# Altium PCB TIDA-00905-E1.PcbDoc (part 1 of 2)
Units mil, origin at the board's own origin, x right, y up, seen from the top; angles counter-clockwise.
Board outline 3740.15 x 5314.95 mil, 4 copper layers (Top Layer, GND, PWR, Bottom Layer), stack 79.834 mil thick; 196 components, 87 nets, 593 pads, 163 vias.
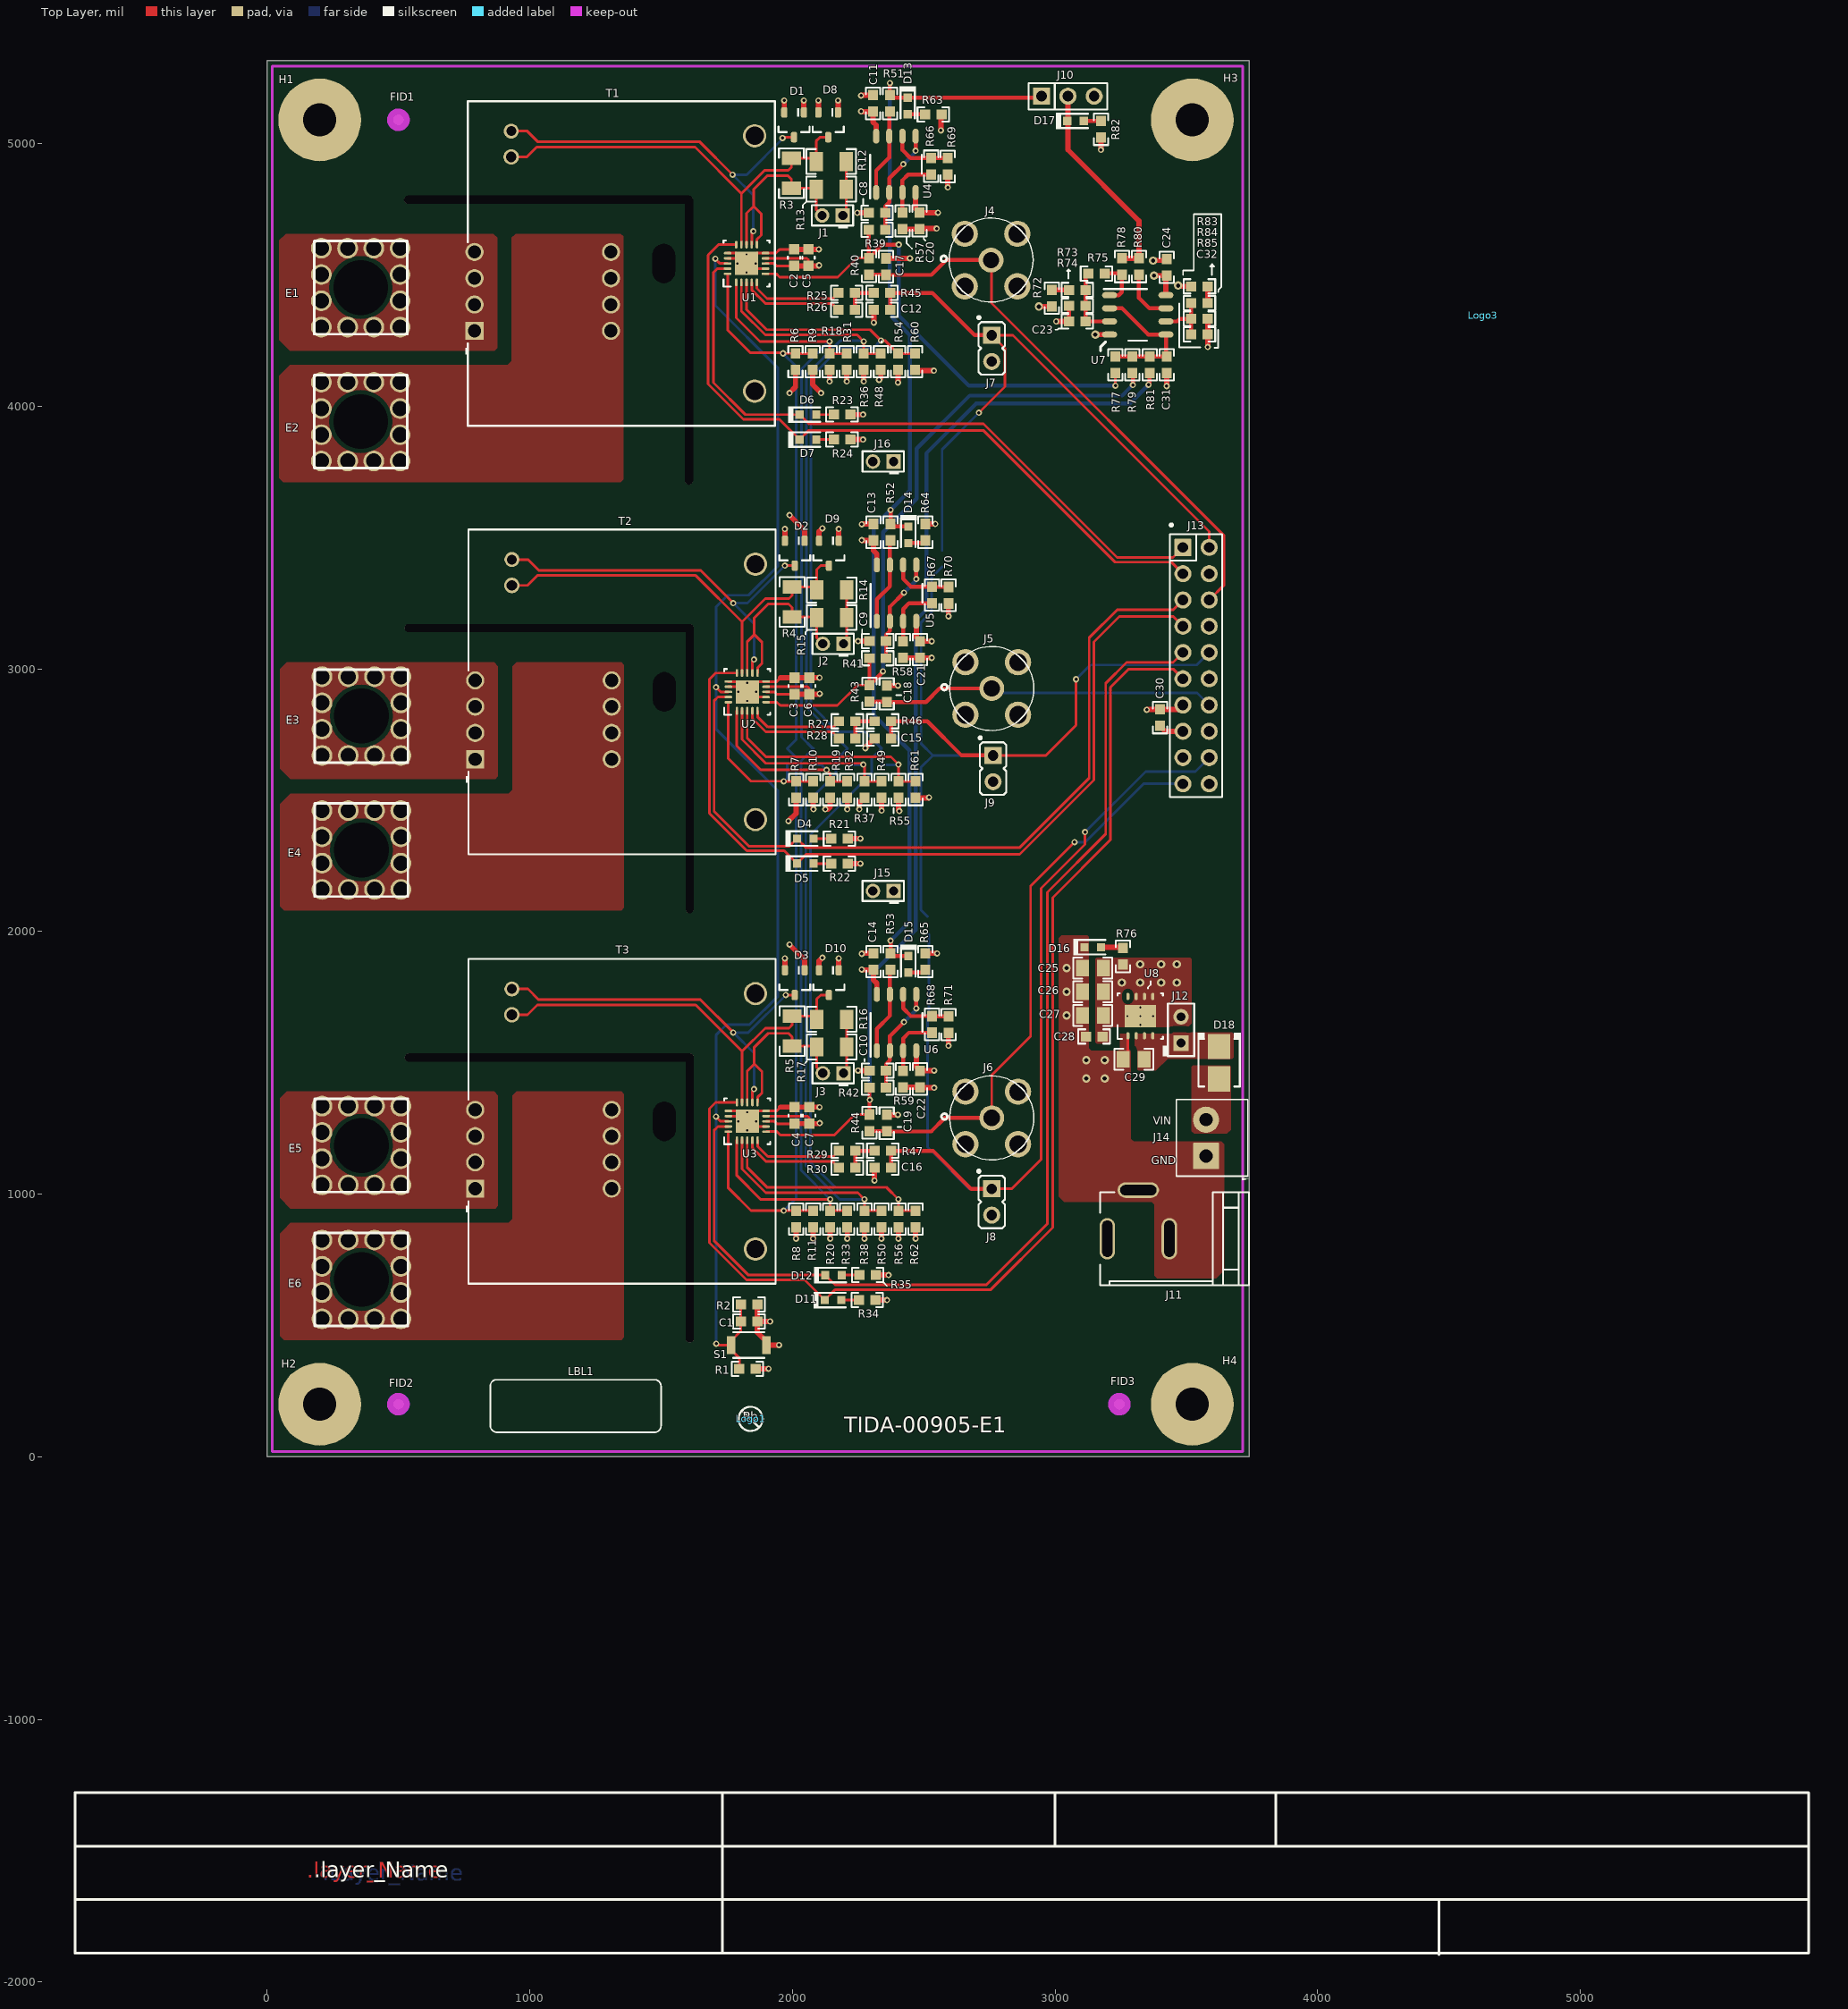
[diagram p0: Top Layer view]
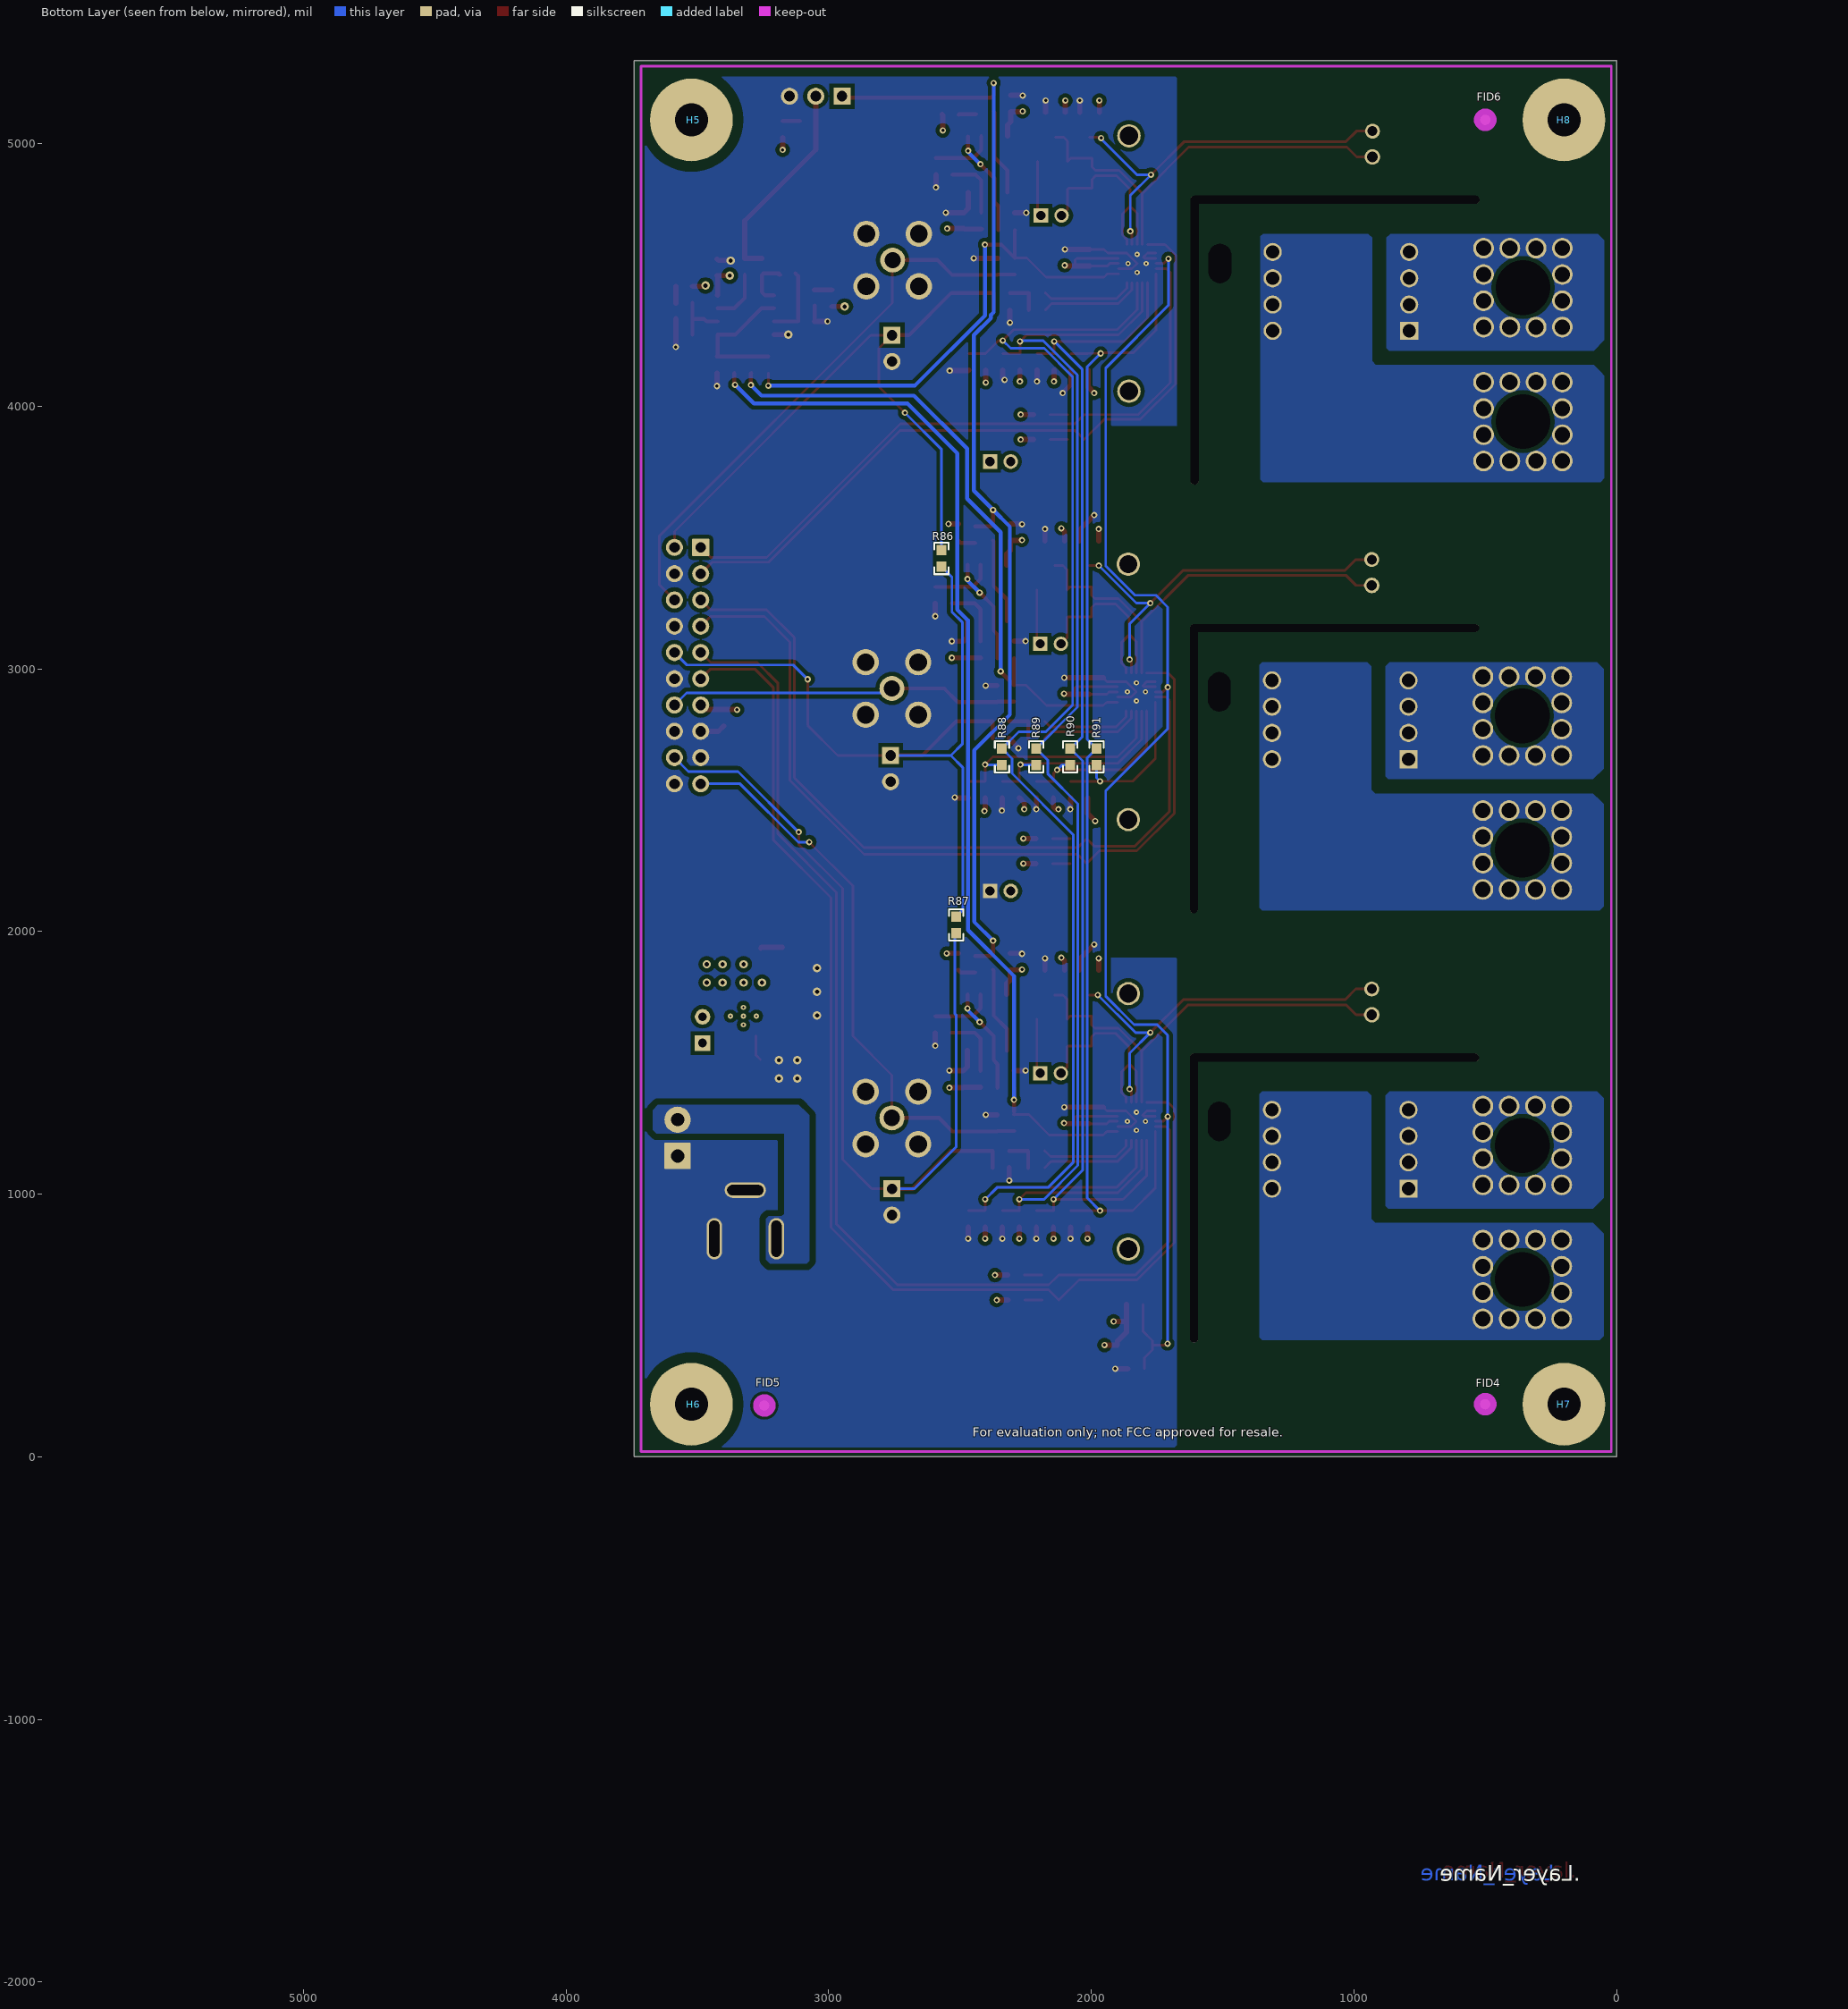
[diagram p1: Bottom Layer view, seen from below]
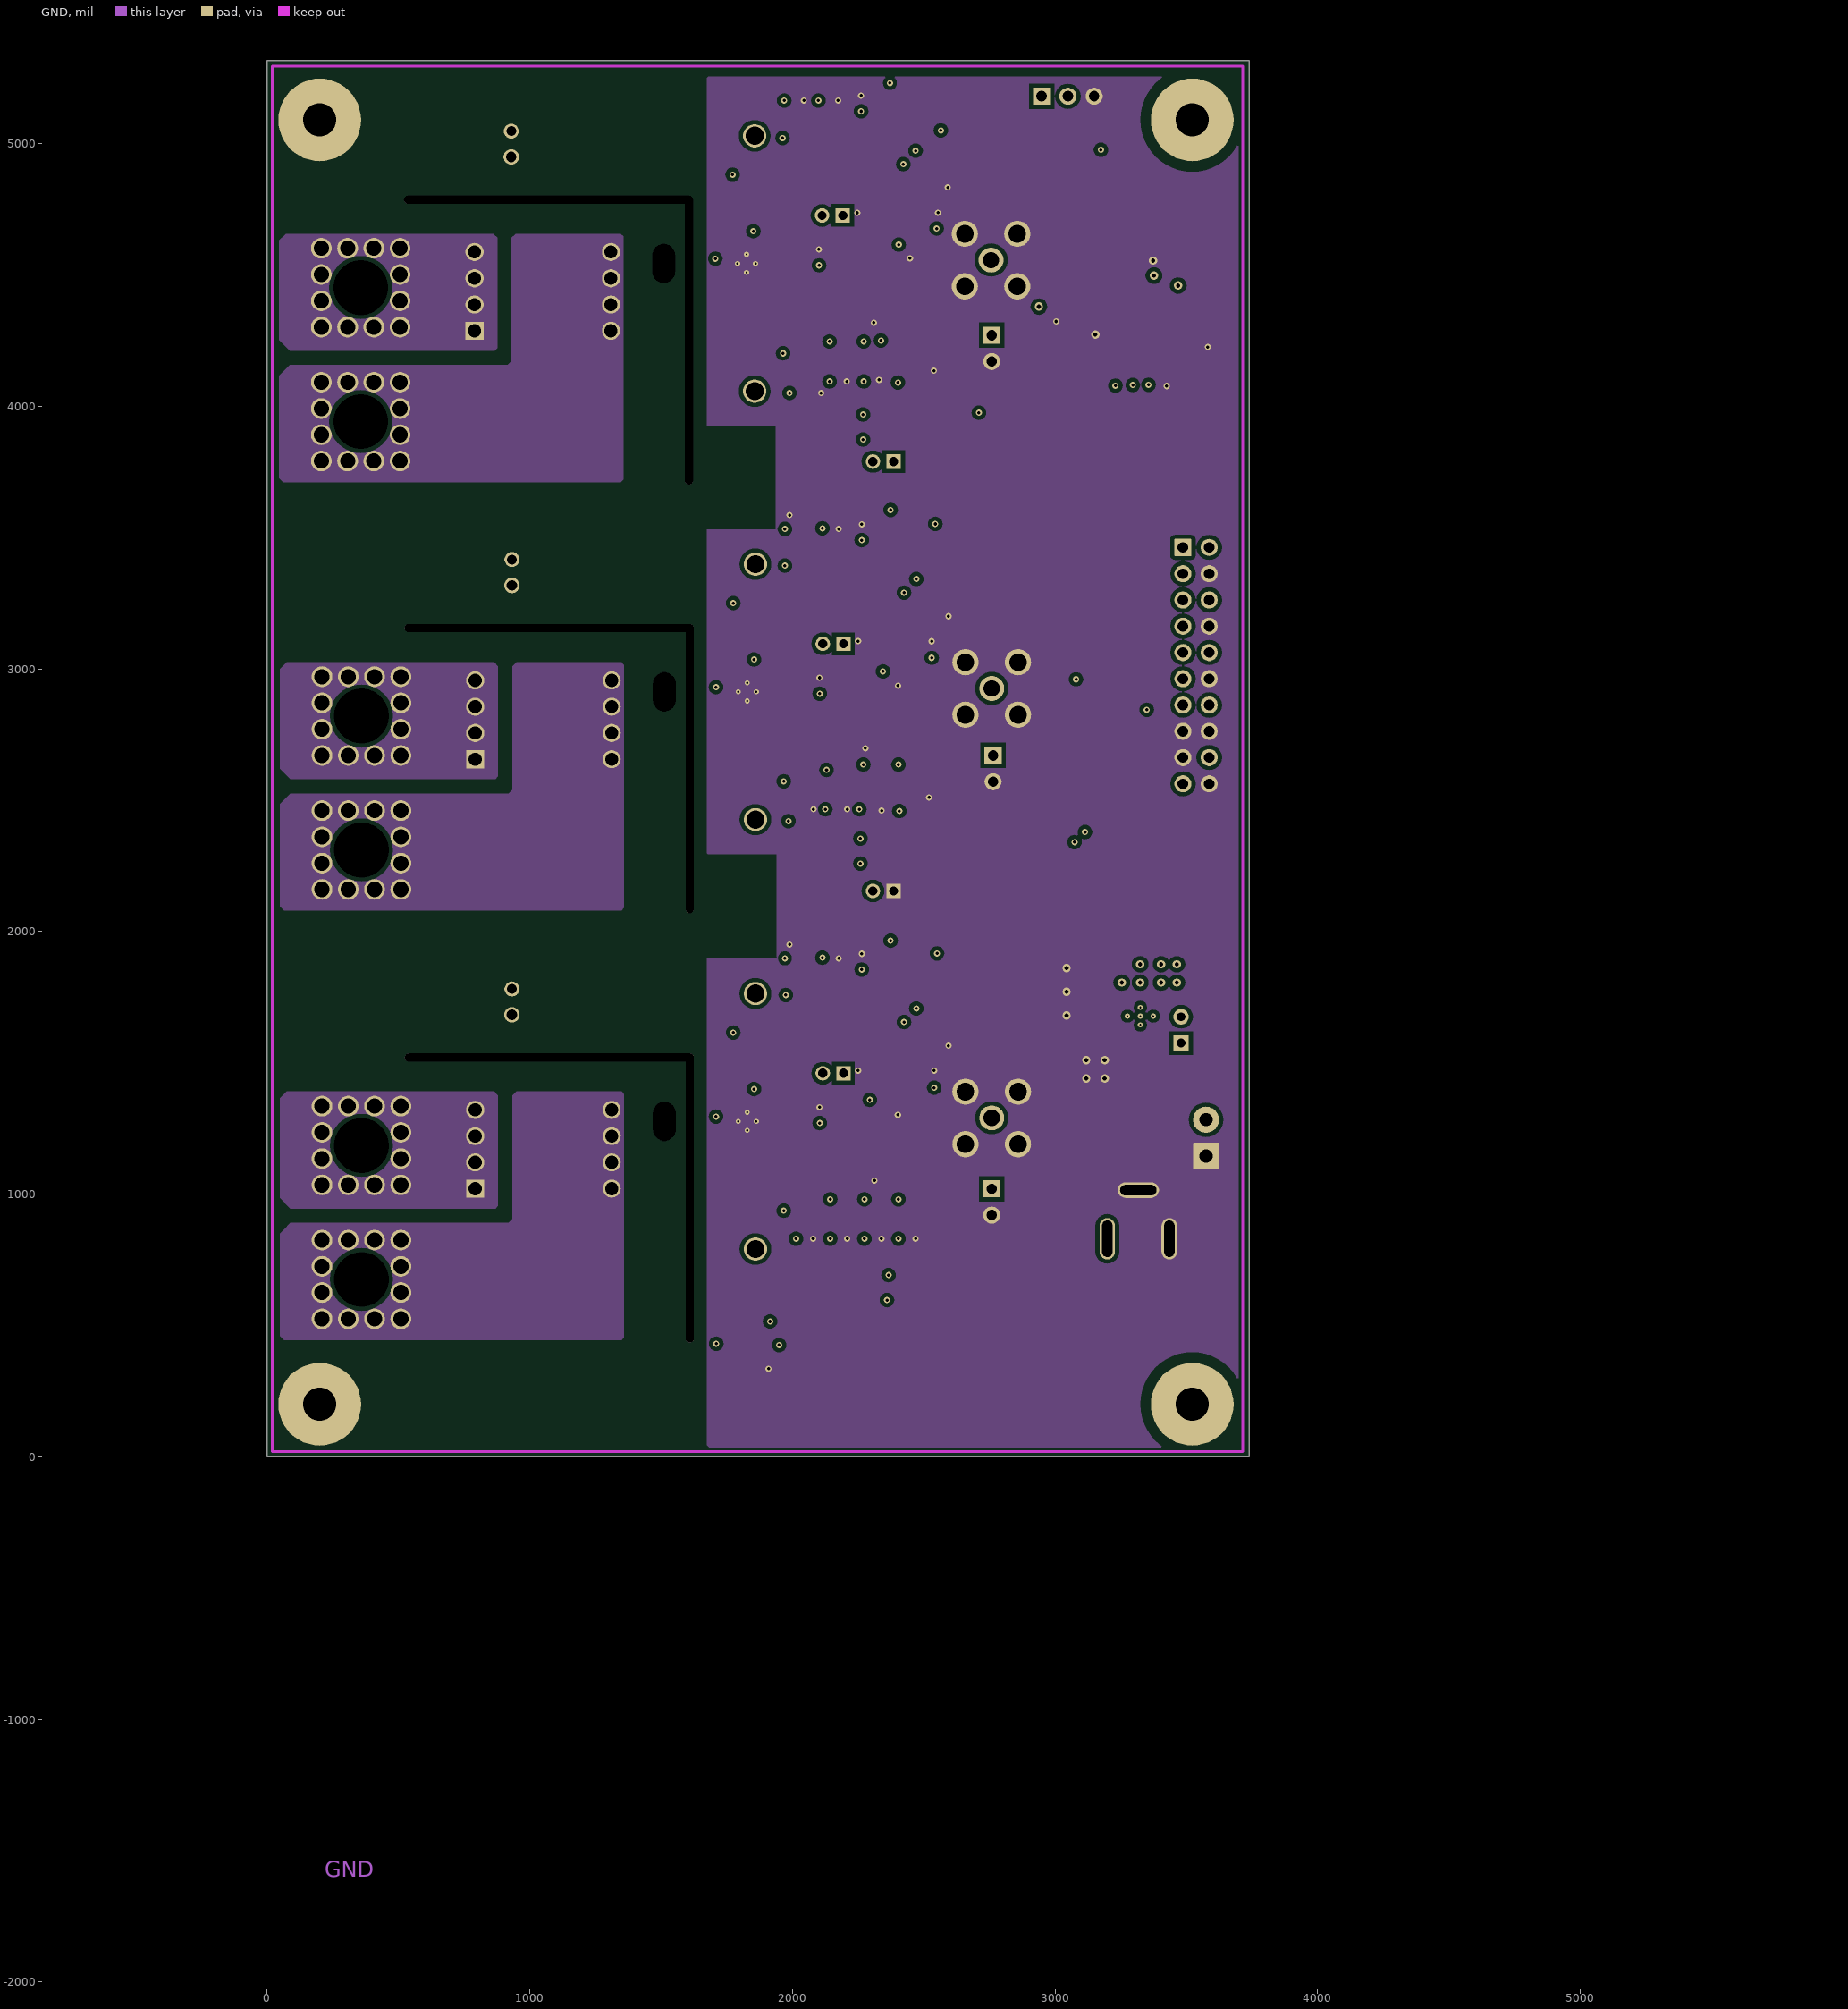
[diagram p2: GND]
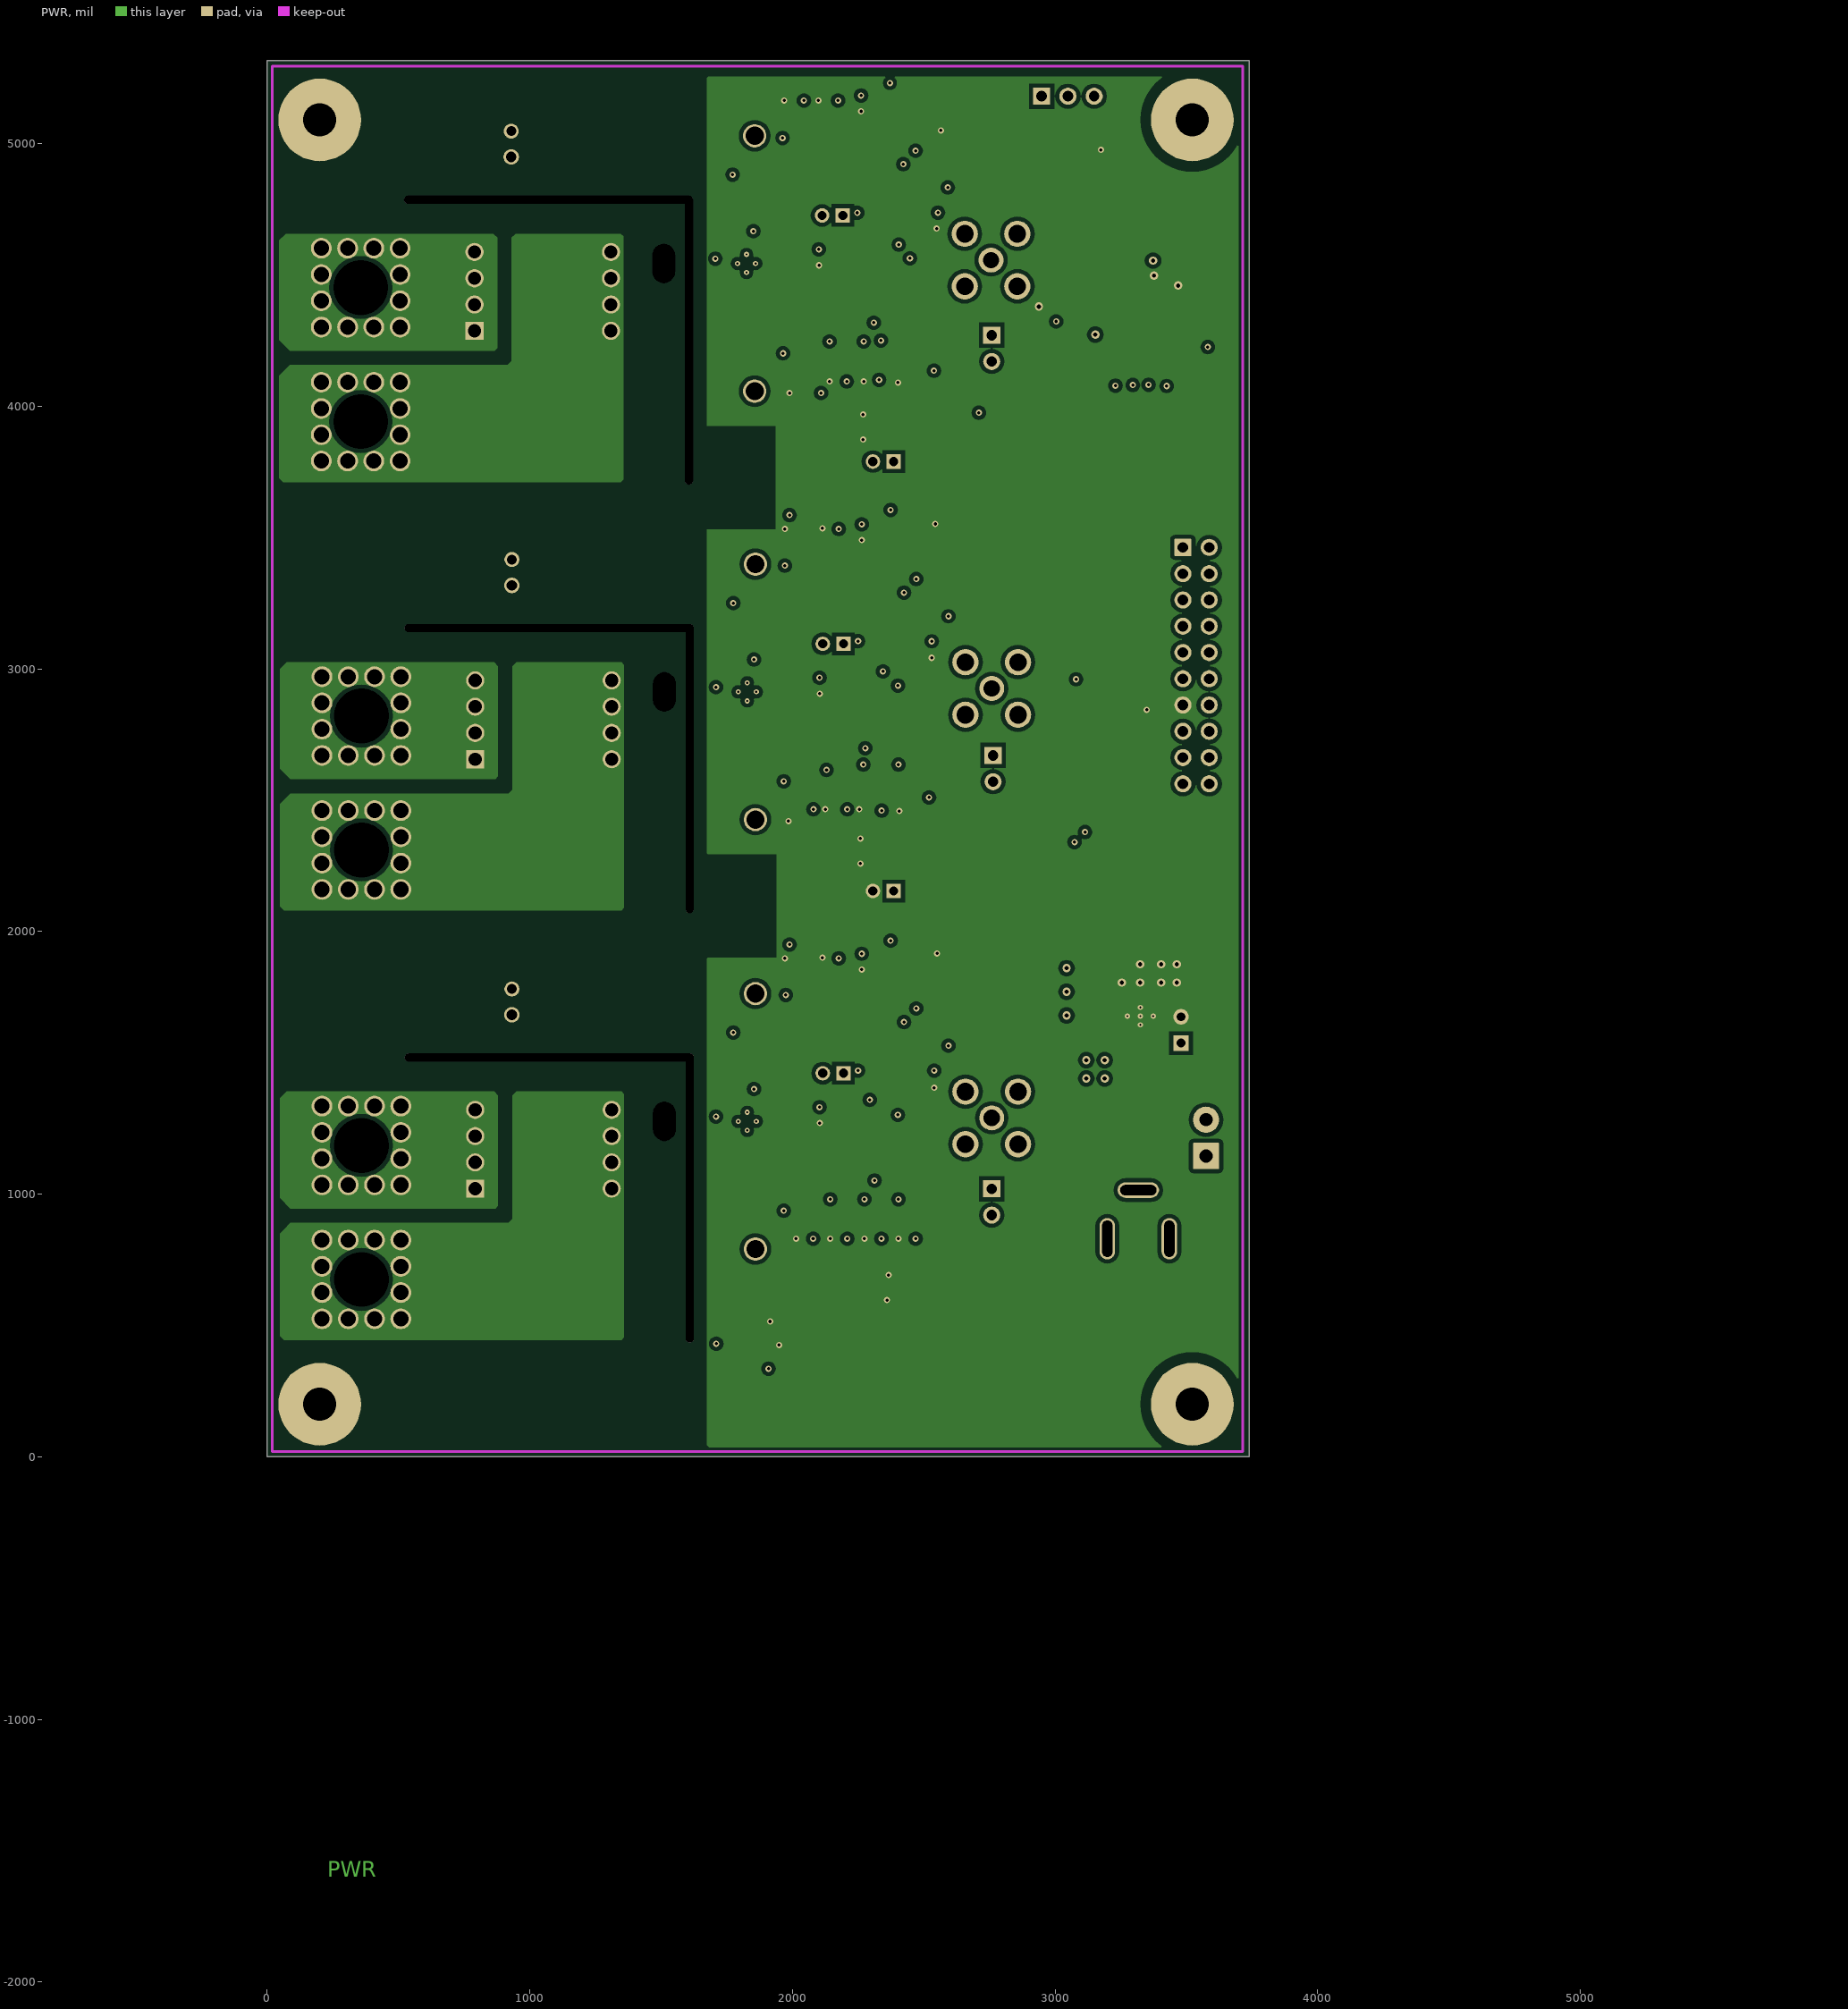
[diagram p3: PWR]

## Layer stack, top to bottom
Top Solder: solder mask 0.4, Solder Resist, Dk 3.5
Top Layer: signal copper 1.4
Dielectric1: core 59.2, FR-4, Dk 4.8
GND: signal copper 1.417
Dielectric 2: prepreg 5, Dk 4.2
PWR: signal copper 1.417
Dielectric 3: core 10, Dk 4.2
Bottom Layer: signal copper 1.4
Bottom Solder: solder mask 0.4, Solder Resist, Dk 3.5

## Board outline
0,0 3740.15,0 3740.15,5314.95 0,5314.95

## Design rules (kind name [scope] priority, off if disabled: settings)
AcuteAngle [All] p1: minimum=4.50000000000000E+0001 checktracksonly=FALSE
AssemblyTestPointUsage [All] p1: valid=2
Clearance Clearance_MTG_COPPER [InPadClass('MTG') vs InPolygon] p1: gap=40
Clearance Clearance_Boardedge_poly [OnCopper and InPolygon vs IsKeepOut] p2: gap=10
Clearance "Clearance_via_thr pin" [IsVia vs IsThruPin] p3: gap=8
Clearance "Shape to Shape" [InPolygon vs InPolygon] p4: gap=25
Clearance "shape to all" [InPolygon] p5: gap=15
Clearance "SMD to Via" [IsSMTPin vs IsVia] p6: gap=8
Clearance [All] p7: gap=8
DiffPairsRouting DiffPair_DiffPairsRouting [InDifferentialPair ('kan')] p1: maxlimit=10 minlimit=10 mostfreqgap=10 toplayer_minwidth=15 toplayer_maxwidth=15 toplayer_prefwidth=15 midlayer1_minwidth=15 midlayer1_maxwidth=15 midlayer1_prefwidth=15 midlayer2_minwidth=15 midlayer2_maxwidth=15 midlayer2_prefwidth=15 bottomlayer_minwidth=15 bottomlayer_maxwidth=15 bottomlayer_prefwidth=15 maxuncoupledlength=500
DiffPairsRouting DiffPair_DiffPairsRouting_1 [InDifferentialPair ('kan')] p2: maxlimit=10 minlimit=10 mostfreqgap=10 toplayer_minwidth=15 toplayer_maxwidth=15 toplayer_prefwidth=15 midlayer1_minwidth=15 midlayer1_maxwidth=15 midlayer1_prefwidth=15 midlayer2_minwidth=15 midlayer2_maxwidth=15 midlayer2_prefwidth=15 bottomlayer_minwidth=15 bottomlayer_maxwidth=15 bottomlayer_prefwidth=15 maxuncoupledlength=500
DiffPairsRouting [All] p3: maxlimit=100 minlimit=10 mostfreqgap=10 toplayer_minwidth=15 toplayer_maxwidth=15 toplayer_prefwidth=15 midlayer1_minwidth=15 midlayer1_maxwidth=15 midlayer1_prefwidth=15 midlayer2_minwidth=15 midlayer2_maxwidth=15 midlayer2_prefwidth=15 bottomlayer_minwidth=15 bottomlayer_maxwidth=15 bottomlayer_prefwidth=15 maxuncoupledlength=1000
FabricationTestPointUsage TestPointUsage [All] p1: valid=2 allowmultiple=FALSE
FabricationTestpoint Testpoint [All] p1: side=3 testpointundercomponent=TRUE minsize=40 maxsize=100 preferedsize=60 minholesize=0 maxholesize=40 preferedholesize=32 testpointgrid=1 allowsidetop=TRUE allowsidebottom=TRUE usegrid=TRUE gridtolerance=0.01
FanoutControl Fanout_LCC [IsLCC] p1: bgadir=Out bgaviamode=Centered fanoutstyle=Auto fanoutdirection=Alternating viagrid=1 // Fanout_LCC (Default Rule)
FanoutControl Fanout_BGA [IsBGA] p2: bgadir=Out bgaviamode=Centered fanoutstyle=Auto fanoutdirection=Alternating viagrid=1 // Fanout_BGA (Default Rule)
FanoutControl Fanout_Default [All] p4: bgadir=Out bgaviamode=Centered fanoutstyle=Auto fanoutdirection=Alternating viagrid=1 // Fanout_Default (Default Rule)
FanoutControl Fanout_Small [(CompPinCount < 5)] p5: bgadir=Out bgaviamode=Centered fanoutstyle=Auto fanoutdirection=OutThenIn viagrid=1 // Fanout_Small (Default Rule)
HoleSize [All] p1: absolutevalues=TRUE maxlimit=1500 minlimit=7 maxpercent=80.000 minpercent=20.000
MatchedLengths DiffPair_MatchedLengths [InDifferentialPair ('kan')] p1: tolerance=1000 checknetsindiffpair=TRUE checkdiffpairvsdiffpair=FALSE checkothers=FALSE
MatchedLengths DiffPair_MatchedLengths_1 [InDifferentialPair ('kan')] p2: tolerance=1000 checknetsindiffpair=TRUE checkdiffpairvsdiffpair=FALSE checkothers=FALSE
MinimumAnnularRing [All] p1: minimumring=5
MinimumAnnularRing MinimumAnnularRing_ThermalPadVias [IsVia and InAnyComponent] p2: minimumring=5.91
MinimumSolderMaskSliver MinimumSolderMaskSliver_Logo [InComponentClass('Logo') vs InComponentClass('Logo')] p1: minsoldermaskwidth=0.7
MinimumSolderMaskSliver [All] p2: minsoldermaskwidth=3.94
PlaneClearance [All] p1: clearance=15
PlaneConnect [All] p1: planeconnectstyle=Direct reliefexpansion=10 reliefentries=4 reliefconductorwidth=10 reliefairgap=10
PolygonConnect [All] p1: connectstyle=Direct reliefconductorwidth=10 reliefentries=4 polygonreliefangle="90 Angle" airgapwidth=10
RoutingVias RoutingVias_power [InNetClass('POWER')] p1: holewidth=16 width=32 viastyle="Through Hole" minholewidth=7.87 minwidth=19.68 maxholewidth=16 maxwidth=32
RoutingVias ThermalPadVias [IsVia and InAnyComponent] p2: holewidth=8 width=20 viastyle="Through Hole" minholewidth=7.87 minwidth=19 maxholewidth=12 maxwidth=24
RoutingVias [All] p3: holewidth=12 width=24 viastyle="Through Hole" minholewidth=12 minwidth=24 maxholewidth=16 maxwidth=32
SMDToCorner [All] p1: distance=30000
SilkToSilkClearance [All] p1: silktosilkclearance=5
SilkToSolderMaskClearance SilkscreenOverComponentPads [IsPad] p1: minsilkscreentomaskgap=5 clearancetoexposedcopper=TRUE
SolderMaskExpansion [All] p1: expansion=3
UnpouredPolygon [All] p1: allowunpoured=FALSE
Width Width_power [InNetClass('pwr')] p1: maxlimit=200 minlimit=8 preferedwidth=20
Width [All] p2: maxlimit=100 minlimit=9 preferedwidth=20 checkconnectedcopper=TRUE
15 further rules are at their usual default settings.

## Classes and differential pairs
component class Label: LBL1
component class AssemblyNote: ZZ1 ZZ2 ZZ3 ZZ4
component class Header: J1 J2 J3 J7 J8 J9 J10 J12 J13 J15 J16
component class "Mounting Holes": H1 H2 H3 H4
pad class MTG: H1-1 H2-1 H3-1 H4-1
component class FiducialMark: FID1 FID2 FID3 FID4 FID5 FID6
component class TIDA-00905-E1_Hardware: FID1 FID2 FID3 FID4 FID5 FID6 H1 H2 H3 H4 H5 H6 H7 H8 LBL1 Logo1 Logo3 ZZ1 ZZ2 ZZ3 ZZ4
component class TIDA-00905-E1_P1: C25 C26 C27 C28 C29 D16 D18 J11 J12 J14 R76 U8
component class TIDA-00905-E1_P2: C3 C4 C6 C7 C9 C10 C13 C14 C15 C16 C18 C19 C21 C22 D2 D3 D4 D5 D9 D10 D11 D12 D14 D15 E3 E4 E5 E6 J2 J3 J5 J6 R4 R5 R7 R8 R10 R11 R14 R15 R16 R17 R19 R20 R21 R22 R27 R28 R29 R30 R32 R33 R34 R35 R37 R38 R41 R42 R43 R44 R46 R47 R49 R50 R52 R53 R55 R56 R58 R59 R61 R62 R64 R65 R67 R68 R70 R71 R88 R89 R90 R91 T2 T3 U2 U3 U5 U6
component class TIDA-00905-E1_P3: C1 C2 C5 C8 C11 C12 C17 C20 D1 D6 D7 D8 D13 E1 E2 J1 J4 J7 J8 J9 J10 R1 R2 R3 R6 R9 R12 R13 R18 R23 R24 R25 R26 R31 R36 R39 R40 R45 R48 R51 R54 R57 R60 R63 R66 R69 R86 R87 S1 T1 U1 U4
component class TIDA-00905-E1_P4: C23 C24 C30 C31 C32 D17 J13 J15 J16 R72 R73 R74 R75 R77 R78 R79 R80 R81 R82 R83 R84 R85 U7

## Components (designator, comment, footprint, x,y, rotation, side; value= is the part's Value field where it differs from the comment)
C1 "0603YC104JAT2A" 0603 1835,515 r180 top (schematic designator C4)
C2 "C0603C105K3RACTU" 0603_095 2006.4,4565.56 r90 top (schematic designator C9)
C3 "C0603C105K3RACTU" 0603_095 2009,2934.45 r90 top (schematic designator C9)
C4 "C0603C105K3RACTU" 0603_095 2009,1299.45 r90 top (schematic designator C9)
C5 "C0603C105K3RACTU" 0603_095 2061.4,4565.56 r90 top (schematic designator C10)
C6 "C0603C105K3RACTU" 0603_095 2064,2934.45 r90 top (schematic designator C10)
C7 "C0603C105K3RACTU" 0603_095 2064,1299.45 r90 top (schematic designator C10)
C8 "0603YC104JAT2A" 0603 2322.4,4736.11 r180 top (schematic designator C30)
C9 "0603YC104JAT2A" 0603 2325,3105 r180 top (schematic designator C30)
C10 "0603YC104JAT2A" 0603 2325,1470 r180 top (schematic designator C30)
C11 "C0603C104J4RACTU" 0603 2306.48,5152.48 r90 top (schematic designator C7)
C12 "0603YC104JAT2A" 0603 2341.4,4366.11 r180 top
C13 "C0603C104J4RACTU" 0603 2309,3520 r90 top (schematic designator C7)
C14 "C0603C104J4RACTU" 0603 2309,1885 r90 top (schematic designator C7)
C15 "0603YC104JAT2A" 0603 2343.98,2735 r180 top (schematic designator C12)
C16 "0603YC104JAT2A" 0603 2344,1100 r180 top (schematic designator C12)
C17 "0603YC104JAT2A" 0603 2356.4,4531.11 r90 top (schematic designator C11)
C18 "0603YC104JAT2A" 0603 2359,2905 r90 top (schematic designator C11)
C19 "0603YC104JAT2A" 0603 2359,1270 r90 top (schematic designator C11)
C20 "C0603C104J4RACTU" 0603 2484,4705.67 r90 top (schematic designator C8)
C21 "C0603C104J4RACTU" 0603 2486.52,3073.19 r90 top (schematic designator C8)
C22 "C0603C104J4RACTU" 0603 2486.52,1438.19 r90 top (schematic designator C8)
C23 "GRM188R71H821KA01D" 0603 3084.97,4322.48 r0 top (schematic designator C25)
C24 "GRM188R71H104KA93D" 0603 3425,4528.66 r270 top (schematic designator C27)
C25 "C2012X5R1A336M125AC" 0805_HV 3144,1860 r180 top (schematic designator C22)
C26 "C2012X5R1A336M125AC" 0805_HV 3144,1770 r180 top (schematic designator C21)
C27 "C2012X5R1A336M125AC" 0805_HV 3144,1680 r180 top (schematic designator C6)
C28 "GRM188R71C104KA01D" 0603 3149,1600 r0 top (schematic designator C23)
C29 "GRM21BR61C106KE15L" 0805_HV 3299.71,1512.56 r180 top (schematic designator C5)
C30 "0603YC104JAT2A" 0603 3399,2814 r270 top (schematic designator C29)
C31 "GRM188R71H821KA01D" 0603 3425.18,4157.31 r90 top (schematic designator C26)
C32 "GRM188R71H821KA01D" 0603 3549.97,4272.48 r180 top (schematic designator C28)
D1 "BAT54S-E3-08" SOT-23 2006.4,5071.11 r270 top (schematic designator D4)
D2 "BAT54S-E3-08" SOT-23 2009,3440 r270 top (schematic designator D4)
D3 "BAT54S-E3-08" SOT-23 2009,1805 r270 top (schematic designator D4)
D4 "150060GS75000" WL-SMCW_GREEN 2049,2353.54 r0 top (schematic designator D6)
D5 "150060GS75000" WL-SMCW_GREEN 2049,2258.54 r0 top
D6 "150060GS75000" WL-SMCW_GREEN 2058.98,3967.73 r0 top
D7 "150060GS75000" WL-SMCW_GREEN 2058.98,3872.73 r0 top (schematic designator D5)
D8 "BAT54S-E3-08" SOT-23 2136.4,5071.11 r270 top (schematic designator D7)
D9 "BAT54S-E3-08" SOT-23 2139,3440 r270 top (schematic designator D7)
D10 "BAT54S-E3-08" SOT-23 2139,1805 r270 top (schematic designator D7)
D11 "150060GS75000" WL-SMCW_GREEN 2155.02,596.46 r0 top (schematic designator D5)
D12 "150060GS75000" WL-SMCW_GREEN 2156.52,691.46 r0 top (schematic designator D6)
D13 "150060GS75000" WL-SMCW_GREEN 2438.92,5142.48 r270 top (schematic designator D3)
D14 "150060GS75000" WL-SMCW_GREEN 2441.44,3510 r270 top (schematic designator D3)
D15 "150060GS75000" WL-SMCW_GREEN 2441.44,1875 r270 top (schematic designator D3)
D16 "150060GS75000" WL-SMCW_GREEN 3144,1940 r0 top (schematic designator LD2)
D17 "150060GS75000" WL-SMCW_GREEN 3078,5086 r0 top (schematic designator D18)
D18 "LSM115JE3/TR13" DO-214BA 3625,1500 r270 top (schematic designator D1)
E1 "7461086" Wurth_7461086 356.4,4451.11 r0 top (schematic designator J12)
E2 "7461086" Wurth_7461086 356.4,3941.11 r0 top (schematic designator J13)
E3 "7461086" Wurth_7461086 359,2820 r0 top (schematic designator J12)
E4 "7461086" Wurth_7461086 359,2310 r0 top (schematic designator J13)
E5 "7461086" Wurth_7461086 359,1185 r0 top (schematic designator J12)
E6 "7461086" Wurth_7461086 359,675 r0 top (schematic designator J13)
FID1 "Fiducial" Fiducial10-20 500,5090 r90 top
FID2 "Fiducial" Fiducial10-20 500,200 r90 top
FID3 "Fiducial" Fiducial10-20 3245,200 r90 top
FID4 "Fiducial" Fiducial10-20 500,200 r90 bottom (schematic designator FID2)
FID5 "Fiducial" Fiducial10-20 3245,195 r90 bottom (schematic designator FID3)
FID6 "Fiducial" Fiducial10-20 500,5090 r90 bottom (schematic designator FID1)
H1 "NY PMS 440 0025 PH" "NY PMS 440 0025 PH" 200,5090 r90 top (schematic designator H2)
H2 "NY PMS 440 0025 PH" "NY PMS 440 0025 PH" 200,200 r180 top (schematic designator H4)
H3 "NY PMS 440 0025 PH" "NY PMS 440 0025 PH" 3522.37,5090 r180 top
H4 "NY PMS 440 0025 PH" "NY PMS 440 0025 PH" 3522.37,200 r90 top (schematic designator H1)
H5 "1902C" Keystone_1902C 3514.37,5090 r0 bottom (schematic designator H7)
H6 "1902C" Keystone_1902C 3514.37,200 r270 bottom
H7 "1902C" Keystone_1902C 200,200 r0 bottom (schematic designator H8)
H8 "1902C" Keystone_1902C 200,5090 r270 bottom (schematic designator H5)
J1 "TMM-102-01-F-S" Samtec_TMM-102-01-F-S 2152.4,4726.11 r180 top (schematic designator J12)
J2 "TMM-102-01-F-S" Samtec_TMM-102-01-F-S 2155,3095 r180 top (schematic designator J12)
J3 "TMM-102-01-F-S" Samtec_TMM-102-01-F-S 2155,1460 r180 top (schematic designator J12)
J4 "142-0701-201" JOHNSON_142-0701-20X 2756.4,4556.11 r0 top (schematic designator J3)
J5 "142-0701-201" JOHNSON_142-0701-20X 2759,2925 r0 top (schematic designator J3)
J6 "142-0701-201" JOHNSON_142-0701-20X 2759,1290 r0 top (schematic designator J3)
J7 "PBC02SAAN" SULLINS_PBC02SAAN 2759,4220 r0 top (schematic designator J9)
J8 "PBC02SAAN" SULLINS_PBC02SAAN 2759,970 r0 top (schematic designator J6)
J9 "PBC02SAAN" SULLINS_PBC02SAAN 2764,2620 r0 top (schematic designator J8)
J10 "PBC03SAAN" PBC03SAAN 3049,5180 r0 top
J11 "PJ-202AH" CONN_CUI-PJ-202AH 3199,830 r0 top locked (schematic designator J4)
J12 "800-10-002-10-001000" Mill-Max_800-10-002-10-001000 3480,1625 r90 top (schematic designator J11)
J13 "TSW-110-07-G-D" TSW-110-07-G-D 3537,3012 r270 top (schematic designator J4)
J14 "ED555/2DS" TERM_BLK_ED555-2DS 3575,1145 r90 top (schematic designator J9)
J15 "TMM-102-01-F-S" Samtec_TMM-102-01-F-S 2346,2154 r180 top
J16 "TMM-102-01-F-S" Samtec_TMM-102-01-F-S 2346,3789 r180 top (schematic designator J15)
LBL1 "Size: 0.65\" x 0.20 \"" Label_650x200 1175,193 r180 top
Logo1 "Pb-Free Symbol" Pb-Free_Overlay_Small 1841,144 r0 top (schematic designator Logo2)
Logo3 "FCC disclaimer" FCC_disclaimer 4629,4345 r180 top
R1 "RC0603JR-0710KL" 0603 1829,335 r180 top (schematic designator R73)
R2 "RC0603JR-070RL" 0603 1835,580 r0 top (schematic designator R88)
R3 "RC1206FR-072R2L" 1206 1996.4,4886.11 r270 top (schematic designator R23)
R4 "RC1206FR-072R2L" 1206 1999,3255 r270 top (schematic designator R23)
R5 "RC1206FR-072R2L" 1206 1999,1620 r270 top (schematic designator R23)
R6 "RC0603JR-0710KL" 0603 2011.73,4169 r270 top (schematic designator R9)
R7 "RC0603JR-0710KL" 0603 2014,2540 r270 top (schematic designator R9)
R8 "RC0603JR-0710KL" 0603 2014,905 r270 top (schematic designator R9)
R9 "ERJ-3GEY0R00V" 0603 2076.73,4169 r270 top (schematic designator R17)
R10 "ERJ-3GEY0R00V" 0603 2079,2540 r270 top (schematic designator R17)
R11 "ERJ-3GEY0R00V" 0603 2079,905 r270 top (schematic designator R17)
R12 "CRCW12061R20FKEA" 1206 2147.4,4931.11 r0 top (schematic designator R22)
R13 "CSR1206FK1R00" 1206 2147.4,4826.11 r180 top (schematic designator R5)
R14 "CRCW12061R20FKEA" 1206 2150,3300 r0 top (schematic designator R22)
R15 "CSR1206FK1R00" 1206 2150,3195 r180 top (schematic designator R5)
R16 "CRCW12061R20FKEA" 1206 2150,1665 r0 top (schematic designator R22)
R17 "CSR1206FK1R00" 1206 2150,1560 r180 top (schematic designator R5)
R18 "RC0603JR-0710KL" 0603 2141.73,4169 r270 top (schematic designator R8)
R19 "RC0603JR-0710KL" 0603 2144,2540 r270 top (schematic designator R8)
R20 "RC0603JR-0710KL" 0603 2144,905 r270 top (schematic designator R8)
R21 "CRCW0603200RJNEA" 0603 2179,2353.54 r0 top (schematic designator R13)
R22 "CRCW0603200RJNEA" 0603 2179,2258.54 r0 top (schematic designator R12)
R23 "CRCW0603200RJNEA" 0603 2188.98,3967.73 r0 top (schematic designator R13)
R24 "CRCW0603200RJNEA" 0603 2188.98,3872.73 r0 top (schematic designator R12)
R25 "CRCW06038R87FKEA" 0603 2206.38,4431.11 r0 top (schematic designator R24)
R26 "ERJ-3GEY0R00V" 0603 2206.4,4366.11 r180 top (schematic designator R25)
R27 "CRCW06038R87FKEA" 0603 2208.96,2800 r0 top (schematic designator R24)
R28 "ERJ-3GEY0R00V" 0603 2208.98,2735 r180 top (schematic designator R25)
R29 "CRCW06038R87FKEA" 0603 2208.98,1165 r0 top (schematic designator R24)
R30 "ERJ-3GEY0R00V" 0603 2209,1100 r180 top (schematic designator R25)
R31 "ERJ-3GEY0R00V" 0603 2206.73,4169 r270 top (schematic designator R16)
R32 "ERJ-3GEY0R00V" 0603 2209,2540 r270 top (schematic designator R16)
R33 "ERJ-3GEY0R00V" 0603 2209,905 r270 top (schematic designator R16)
R34 "CRCW0603200RJNEA" 0603 2285.02,596.46 r0 top (schematic designator R12)
R35 "CRCW0603200RJNEA" 0603 2286.52,691.46 r0 top (schematic designator R13)
R36 "RC0603JR-0710KL" 0603 2271.73,4169 r270 top (schematic designator R7)
R37 "RC0603JR-0710KL" 0603 2274,2540 r270 top (schematic designator R7)
R38 "RC0603JR-0710KL" 0603 2274,905 r270 top (schematic designator R7)
R39 "RC0603JR-070RL" 0603 2322.4,4671.11 r0 top (schematic designator R86)
R40 "RC0603JR-070RL" 0603 2291.4,4532.57 r270 top (schematic designator R20)
R41 "RC0603JR-070RL" 0603 2325,3040 r0 top (schematic designator R86)
R42 "RC0603JR-070RL" 0603 2325,1405 r0 top (schematic designator R86)
R43 "RC0603JR-070RL" 0603 2294,2906.46 r270 top (schematic designator R20)
R44 "RC0603JR-070RL" 0603 2294,1271.46 r270 top (schematic designator R20)
R45 "ERJ-3GEY0R00V" 0603 2341.4,4431.11 r0 top (schematic designator R26)
R46 "ERJ-3GEY0R00V" 0603 2343.98,2800 r0 top (schematic designator R26)
R47 "ERJ-3GEY0R00V" 0603 2344,1165 r0 top (schematic designator R26)
R48 "ERJ-3GEY0R00V" 0603 2336.73,4169 r270 top (schematic designator R15)
R49 "ERJ-3GEY0R00V" 0603 2339,2540 r270 top (schematic designator R15)
R50 "ERJ-3GEY0R00V" 0603 2339,905 r270 top (schematic designator R15)
R51 "RC0603JR-070RL" 0603 2371.48,5152.48 r90 top (schematic designator R18)
R52 "RC0603JR-070RL" 0603 2374,3520 r90 top (schematic designator R18)
R53 "RC0603JR-070RL" 0603 2374,1885 r90 top (schematic designator R18)
R54 "RC0603JR-0710KL" 0603 2401.73,4169 r270 top (schematic designator R6)
R55 "RC0603JR-0710KL" 0603 2404,2540 r270 top (schematic designator R6)
R56 "RC0603JR-0710KL" 0603 2404,905 r270 top (schematic designator R6)
R57 "RG1608P-122-B-T5" 0603 2419,4705.67 r270 top (schematic designator R11)
R58 "RG1608P-122-B-T5" 0603 2421.52,3073.19 r270 top (schematic designator R11)
R59 "RG1608P-122-B-T5" 0603 2421.52,1438.19 r270 top (schematic designator R11)
R60 "ERJ-3GEY0R00V" 0603 2466.73,4169 r270 top (schematic designator R14)
R61 "ERJ-3GEY0R00V" 0603 2469,2540 r270 top (schematic designator R14)
R62 "ERJ-3GEY0R00V" 0603 2469,905 r270 top (schematic designator R14)
R63 "CRCW0603200RJNEA" 0603 2536.48,5110.08 r0 top (schematic designator R10)
R64 "CRCW0603200RJNEA" 0603 2506.44,3520 r90 top (schematic designator R10)
R65 "CRCW0603200RJNEA" 0603 2506.44,1885 r90 top (schematic designator R10)
R66 "RT0603BRD076K98L" 0603 2528.75,4913.48 r270 top (schematic designator R19)
R67 "RT0603BRD076K98L" 0603 2531.27,3281 r270 top (schematic designator R19)
R68 "RT0603BRD076K98L" 0603 2531.27,1646 r270 top (schematic designator R19)
R69 "RG1608P-122-B-T5" 0603 2591.48,4912.48 r90 top (schematic designator R21)
R70 "RG1608P-122-B-T5" 0603 2594,3280 r90 top (schematic designator R21)
R71 "RG1608P-122-B-T5" 0603 2594,1645 r90 top (schematic designator R21)
R72 "ERJ-3GEY0R00V" 0603 2987.66,4411 r90 top (schematic designator R87)
R73 "RG1608P-1072-B-T5" 0603 3084.97,4442.48 r0 top (schematic designator R69)
R74 "RT0603BRD0711KL" 0603 3084.97,4382.48 r180 top (schematic designator R72)
R75 "CRCW06035M11FKEA" 0603 3157.66,4505 r0 top (schematic designator R70)
R76 "CRCW0603750RJNEA" 0603 3259,1905 r270 top (schematic designator R85)
R77 "PHT0603Y1002BGT200" 0603 3229.97,4157.48 r90 top
R78 "RC0603JR-070RL" 0603 3254.43,4531.48 r90 top (schematic designator R74)
R79 "PHT0603Y1002BGT200" 0603 3294.97,4157.48 r90 top (schematic designator R76)
R80 "RC0603JR-070RL" 0603 3319.43,4531.48 r90 top (schematic designator R78)
R81 "PHT0603Y1002BGT200" 0603 3359.97,4157.48 r90 top (schematic designator R75)
R82 "CRCW0603200RJNEA" 0603 3175,5054 r270 top (schematic designator R71)
R83 "ERJ-3GEY0R00V" 0603 3550,4456 r0 top (schematic designator R86)
R84 "RT0603BRD0711KL" 0603 3549.97,4392.48 r180 top (schematic designator R79)
R85 "RG1608P-1072-B-T5" 0603 3549.97,4332.48 r0 top (schematic designator R80)
R86 "RC0603JR-070RL" 0603 2570,3420 r90 bottom (schematic designator R89)
R87 "RC0603JR-070RL" 0603 2515,2025 r90 bottom
R88 "RC0603JR-070RL" 0603 2340,2665 r270 bottom (schematic designator R1)
R89 "RC0603JR-070RL" 0603 2210,2665 r270 bottom (schematic designator R81)
R90 "RC0603JR-070RL" 0603 2080,2665 r270 bottom (schematic designator R83)
R91 "RC0603JR-070RL" 0603 1980,2665 r270 bottom (schematic designator R85)
S1 "B3U-1000P" SW_B3U-1000P 1834,425 r180 top
T1 "SC3113-50" Sumida_SC3113 1801.4,4543.11 r90 top
T2 "SC3113-50" Sumida_SC3113 1804,2912 r90 top (schematic designator T1)
T3 "SC3113-50" Sumida_SC3113 1804,1277 r90 top (schematic designator T1)
U1 "DRV421RTJR" RTJ0020G 1825.4,4543.11 r90 top locked (schematic designator U3)
U2 "DRV421RTJR" RTJ0020G 1828,2912 r90 top locked (schematic designator U3)
U3 "DRV421RTJR" RTJ0020G 1828,1277 r90 top locked
U4 "TLC372QDR" D0008A_N 2394,4920.67 r90 top (schematic designator U2)
U5 "TLC372QDR" D0008A_N 2396.52,3288.19 r90 top (schematic designator U2)
U6 "TLC372QDR" D0008A_N 2396.52,1653.19 r90 top (schematic designator U2)
U7 "TLC372QDR" D0008A_N 3314.97,4347.48 r0 top (schematic designator U8)
U8 "TLV1117-33IDRJR" DRJ0008A 3324.71,1677.56 r90 top (schematic designator U1)
ZZ1 "This Assembly Note is for PCB labels only" AssemblyNoteLabel 97,5833 r0 top
ZZ2 "These assemblies are ESD sensitive, ESD precautions shall be observed." AssemblyNote 1447,8394 r0 top
ZZ3 "These assemblies must be clean and free from flux and all contaminants. Use of no clean flux is not acceptable." AssemblyNote 1447,8309 r0 top
ZZ4 "These assemblies must comply with workmanship standards IPC-A-610 Class 2, unless otherwise specified." AssemblyNote 1447,8234 r0 top

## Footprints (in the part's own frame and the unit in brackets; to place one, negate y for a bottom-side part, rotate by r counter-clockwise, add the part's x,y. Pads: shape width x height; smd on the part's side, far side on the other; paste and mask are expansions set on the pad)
0603 [mm] "0603 from SM-752 data"
  rect 1x0.95 smd: 1(-0.8,0) 2(0.8,0)
  silkscreen extent -1.52,-0.69 1.52,0.69, body extent -0.87,-0.47 0.87,0.47, height 1
0603_095 [mm] "0603_095"
  rect 1x1 smd: 1(-0.8,0) 2(0.8,0)
  silkscreen extent -0.1,-0.6 0.1,0.6, body extent -0.87,-0.48 0.87,0.48, height 0.95
0805_HV [mil] "0805 with 30mil clearance between pads"
  rect 50x63 smd: 1(-40,0) 2(40,0)
  silkscreen extent -74,-40 74,40, body extent -43,-29 43,29, height 43
1206 [mm] "1206 from SM-752 data"
  rect 1.3x1.85 smd: 1(-1.45,0) 2(1.45,0)
  silkscreen extent -2.4,-1.21 2.4,1.21, body extent -1.7,-0.9 1.7,0.9, height 1.35
AssemblyNote [mil] "Assembly Note"
AssemblyNoteLabel [mil] "Assembly Note for PCB Labels"
CONN_CUI-PJ-202AH [mm] "Conn_DC Jack"
  oval 1.5x4 hole 1 slot 3.5 at 90 deg: 1(0,0) 2(6,0)
  oval 4x1.5 hole 1 slot 3.5 at 0 deg: 3(3,4.7)
  silkscreen extent -0.7,-4.5 13.7,4.5, body extent -0.7,-4.5 13.7,4.9, height 11.02
D0008A_N [mm] "SOIC, 8-Leads, Body 4.9x3.9mm, Pitch 1.27mm, IPC Medium Density"
  oval 1.45x0.6 smd: 1(-2.725,1.905) 2(-2.725,0.635) 3(-2.725,-0.635) 4(-2.725,-1.905) 5(2.725,-1.905) 6(2.725,-0.635) 7(2.725,0.635) 8(2.725,1.905)
  silkscreen extent -3.3,-2.5 0.9,2.5, body extent -3,-2.45 3,2.45, height 1.63
DO-214BA [mm] "Molded Diode, 2-Leads, Body 4.3x3.6mm, IPC Medium Density"
  rect 2.45x2.15 smd: 1(-1.575,0) 2(1.575,0)
  silkscreen extent -2.92,-2.1 2.3,2.1, body extent -2.29,-1.97 2.28,1.97, height 3.3
DRJ0008A [mm] "SON, 8-Leads, Body 4x4mm, Pitch 0.8mm, Thermal Pad 3x2.2mm, TI Recommended"
  oval 0.7x0.3 smd: 1(-1.9,1.2) 2(-1.9,0.4) 3(-1.9,-0.4) 4(-1.9,-1.2) 5(1.9,-1.2) 6(1.9,-0.4) 7(1.9,0.4) 8(1.9,1.2)
  rect 2.2x3 smd paste-1.1: 9(0,0)
  silkscreen extent -2.2,-2.2 2.2,2.2, body extent -2.05,-2.05 2.05,2.05, height 0.81
FCC_disclaimer [mil]
Fiducial10-20 [mm]
  round 1 smd mask+0.5: 1(0,0)
  Top Layer keep-out circle w1.178: c0,0 r0.5
JOHNSON_142-0701-20X [mil] "Johnson Components recommended land pattern"
  round 95 hole 62: 1(0,0)
  round 100 hole 67: 2(100,100) 3(100,-100) 4(-100,-100) 5(-100,100)
  silkscreen extent -191,-160 160,160, body extent -156,-156 156,156, height 375
Keystone_1902C [mil] "Hex Standoff, 4-40 threaded, nylon"
  round 1 on Mech4: 0(0,0)
  body extent -145,-126 146,126, height 501
Label_650x200 [mil] "Thermal Transfer Label"
  round 1 on Mech13: 0(0,0)
  silkscreen extent -325,-100 325,100, body extent -326,-101 326,101, height 1
Mill-Max_800-10-002-10-001000 [mm] "Mill-Max"
  rect 1.5x1.5 hole 0.85: 1(-1.27,0)
  round 1.5 hole 0.85: 2(1.27,0)
  silkscreen extent -2.54,-1.27 2.54,1.78, body extent -2.54,-1.27 2.54,1.27, height 8.13
"NY PMS 440 0025 PH" [mm] "4-40 nylon screw and mounting hole"
  round 8 hole 3.2: 1(0,0)
  body extent -3.3,-3.3 3.3,3.3, height 2.69
Pb-Free_Overlay_Small [mil]
  silkscreen extent -46,-46 46,46
PBC03SAAN [mm] "Sullins 100mil, 1x3, 230 mil above insulator"
  rect 1.65x1.65 hole 1.016: 1(-2.54,0)
  round 1.65 hole 1.016: 2(0,0) 3(2.54,0)
  silkscreen extent -3.81,-1.27 3.81,1.27, body extent -3.81,-1.27 3.81,1.27, height 8.38
RTJ0020G [mm] "QFN, 20-Leads, Body 4x4mm, Pitch 0.5mm, Thermal Pad 2.25x2.25mm, TI Recommended"
  oval 0.75x0.24 smd: 1(-1.825,1) 2(-1.825,0.5) 3(-1.825,0) 4(-1.825,-0.5) 5(-1.825,-1) 11(1.825,-1) 12(1.825,-0.5) 13(1.825,0) 14(1.825,0.5) 15(1.825,1)
  oval 0.24x0.75 smd: 6(-1,-1.825) 7(-0.5,-1.825) 8(0,-1.825) 9(0.5,-1.825) 10(1,-1.825) 16(1,1.825) 17(0.5,1.825) 18(0,1.825) 19(-0.5,1.825) 20(-1,1.825)
  rect 2.25x2.25 smd paste-1.125: 21(0,0)
  silkscreen extent -2.23,-2.23 2.23,2.23, body extent -2.07,-2.07 2.08,2.08, height 0.81
Samtec_TMM-102-01-F-S [mm] "Header, 2mm, 2x1, TH"
  rect 1.4x1.4 hole 0.89: 1(-1,0)
  round 1.4 hole 0.89: 2(1,0)
  silkscreen extent -2,-0.98 2,1.25, body extent -2,-0.99 2,0.99, height 4.71
SOT-23 [mm] "SOT23, 3-Leads, Body 2.9x1.3mm, Pitch 0.95mm, Lead Span 2.5mm, IPC Medium Density"
  rrect50% 1x0.6 smd: 1(-1.2,0.95) 2(-1.2,-0.95) 3(1.2,0)
  silkscreen extent -1.63,-1.5 0.7,1.5, body extent -1.16,-1.45 1.21,1.45, height 1
SULLINS_PBC02SAAN [mm] "Sullins 100mil, 1x2, 230 mil above insulator"
  rect 1.65x1.65 hole 1.016: 1(0,1.27)
  round 1.65 hole 1.016: 2(0,-1.27)
  silkscreen extent -1.37,-2.54 1.27,3.1, body extent -1.27,-2.54 1.27,2.54, height 8.38
Sumida_SC3113 [mm] "TH, 10-Leads, Body 31.3x29.6mm"
  rect 1.75x1.75 hole 1.27: 1(-6.51,25.7)
  round 1.75 hole 1.27: 2(-3.97,25.7) 3(-1.43,25.7) 4(1.11,25.7) 5(-6.51,12.5) 6(-3.97,12.5) 7(-1.43,12.5) 8(1.11,12.5)
  round 1.5 hole 1.016: 9(10.3,22.15)
  round 1.45 hole 0.95: 10(12.8,22.15)
  round 0 hole 2.2 slot 3.8 at 0 deg: MH1(0,7.4)
  round 2.25 hole 1.75: MH2(-12.35,-1.4) MH3(12.35,-1.4)
  silkscreen extent -15.7,-3.35 15.7,26.6, body extent -15.7,-3.35 15.7,26.35, height 13.3
SW_B3U-1000P [mm] "OMRON"
  rect 0.8x1.7 smd: 1(-1.7,0) 2(1.7,0)
  silkscreen extent -1.5,-1.25 1.5,1.25, body extent -1.5,-1.25 1.5,1.25, height 1.75
TERM_BLK_ED555-2DS [mil]
  rrect4% 100x100 hole 50: 1(0,0)
  round 100 hole 50: 2(138,0)
  silkscreen extent -93,-161 215,113, body extent -69,-150 207,106, height 323
TSW-110-07-G-D [mm] "Samtec 100mil, 2x10, 230 mil above insulator"
  rrect6% 1.65x1.65 hole 1.016: 1(-11.43,-1.27)
  round 1.65 hole 1.016: 2(-11.43,1.27) 3(-8.89,-1.27) 4(-8.89,1.27) 5(-6.35,-1.27) 6(-6.35,1.27) 7(-3.81,-1.27) 8(-3.81,1.27) 9(-1.27,-1.27) 10(-1.27,1.27) 11(1.27,-1.27) 12(1.27,1.27) 13(3.81,-1.27) 14(3.81,1.27) 15(6.35,-1.27) 16(6.35,1.27) 17(8.89,-1.27) 18(8.89,1.27) 19(11.43,-1.27) 20(11.43,1.27)
  silkscreen extent -13.72,-2.54 12.7,2.54, body extent -12.7,-2.54 12.7,2.54, height 8.38
WL-SMCW_GREEN [mm] "WURTH"
  rect 0.8x0.8 smd: 1(-0.8,0) 2(0.8,0)
  silkscreen extent -1.9,-0.8 1.2,0.8, body extent -0.85,-0.45 0.85,0.45, height 0.8
Wurth_7461086 [mm] "Bush, M4, TH"
  round 2 hole 1.475: 1(-3.81,-3.81) 1(-3.81,-1.27) 1(-3.81,1.27) 1(-3.81,3.81) 1(-1.27,-3.81) 1(-1.27,3.81) 1(1.27,-3.81) 1(1.27,3.81) 1(3.81,-3.81) 1(3.81,-1.27) 1(3.81,1.27) 1(3.81,3.81)
  round 0 hole 5.3 unplated: ""(0,0)
  body extent -4.5,-4.5 4.5,4.5, height 6.1

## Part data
C1 C8 C9 C10 C12 C15 C16 C17 C18 C19 C30: "CAP, CERM, 0.1 µF, 16 V, +/- 5%, X7R, 0603"
C2 C3 C4 C5 C6 C7: "CAP, CERM, 1 µF, 25 V, +/- 10%, X7R, 0603_095"
C11 C13 C14 C20 C21 C22: "CAP, CERM, 0.1uF, 16V, +/-5%, X7R, 0603"
C23 C31 C32: "CAP, CERM, 820 pF, 50 V, +/- 10%, X7R, 0603"
C24: "CAP, CERM, 0.1 µF, 50 V, +/- 10%, X7R, 0603"
C25 C26 C27: "CAP, CERM, 33 µF, 10 V, +/- 20%, X5R, 0805"
C28: "CAP, CERM, 0.1 µF, 16 V, +/- 10%, X7R, 0603"
C29: "CAP, CERM, 10uF, 16V, +/-10%, X5R, 0805"
D1 D2 D3 D8 D9 D10: "Diode, Schottky, 30 V, 0.2 A, SOT-23"
D4 D5 D6 D7 D11 D12 D13 D14 D15 D16 D17: "LED, Green, SMD"
D18: "Diode, Schottky, 15 V, 1 A, DO-214BA"
E1 E2 E3 E4 E5 E6: "Power Element Bush, M4, 12, TH"
FID1 FID2 FID3 FID4 FID5 FID6: "Fiducial mark.  There is nothing to buy or mount."
H1 H2 H3 H4: "Machine Screw, Round, #4-40 x 1/4, Nylon, Philips panhead"
H5 H6 H7 H8: "Standoff, Hex, 0.5\"L #4-40 Nylon"
J1 J2 J3 J15 J16: "Header, 2mm, 2x1, Gold, TH"
J4 J5 J6: "Connector, TH, SMA"
J7 J8 J9: "Header, 100mil, 2x1, Gold, TH"
J10: "Header, 100mil, 3x1, Gold, TH"
J11: "Connector, DC Jack 2.1X5.5 mm, TH"
J12: "Header, 100mil, 2x1, TH"
J13: "Header, 100mil, 10x2, Gold, TH"
J14: "Terminal Block, 3.5mm Pitch, 2x1, TH"
LBL1: library part THT-14-423-10, "Thermal Transfer Printable Labels, 0.650\" W x 0.200\" H - 10,000 per roll"
Logo1: library part Pb-Free
Logo3: library part FCC_disclaimer, "FCC_disclaimer"
R1 R6 R7 R8 R18 R19 R20 R36 R37 R38 R54 R55 R56: "RES, 10 k, 5%, 0.1 W, 0603"
R2 R9 R10 R11 R26 R28 R30 R31 R32 R33 R39 R40 R41 R42 R43 R44 R45 R46 R47 R48 R49 R50 R51 R52 R53 R60 R61 R62 R72 R78 R80 R83 R86 R87 R88 R89 R90 R91: "RES, 0, 5%, 0.1 W, 0603"
R3 R4 R5: "RES, 2.20, 1%, 0.25 W, 1206"
R12 R14 R16: "RES, 1.20, 1%, 0.25 W, AEC-Q200 Grade 0, 1206"
R13 R15 R17: "RES, 1.00, 1%, 0.5 W, 1206"
R21 R22 R23 R24 R34 R35 R63 R64 R65 R82: "RES, 200, 5%, 0.1 W, 0603"
R25 R27 R29: "RES, 8.87, 1%, 0.1 W, 0603"
R57 R58 R59 R69 R70 R71: "RES, 1.20 k, 0.1%, 0.1 W, 0603"
R66 R67 R68: "RES, 6.98 k, 0.1%, 0.1 W, 0603"
R73 R85: "RES, 10.7 k, 0.1%, 0.1 W, 0603"
R74 R84: "RES, 11.0 k, 0.1%, 0.1 W, 0603"
R75: "RES, 5.11 M, 1%, 0.1 W, 0603"
R76: "RES, 750, 5%, 0.1 W, 0603"
R77 R79 R81: "RES, 10.0 k, 0.1%, 0.0375 W, 0603"
S1: "SWITCH TACTILE SPST-NO 0.05A 12V"
T1 T2 T3: "Transformer, TH"
U1 U2 U3: "5-V, Closed-Loop, Current Sense Conditioner with Integrated Fluxgate Sensor, RTJ0020G"
U4 U5 U6 U7: "LinCMOS Dual Differential Comparators, D0008A"
U8: "LDO with 4.7 to 15 V Input and 3.3 V Output, -40 to 125 degC, 8-Pin SON (DRJ), Green (RoHS & no Sb/Br)"
ZZ1: library part AssemblyNoteLabel
ZZ2 ZZ3 ZZ4: library part AssemblyNote

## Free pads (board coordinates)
  oval 1100x30 hole 30 slot 1100 at 0 deg unplated paste+5 mask+5: 0(1071.4,4786.11) 0(1074,1520) 0(1074,3155)
  oval 30x1100 hole 30 slot 1100 at 90 deg unplated paste+5 mask+5: 0(1606.4,4251.11) 0(1609,985) 0(1609,2620)

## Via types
v1: diameter 24, hole 12, Top Layer to Bottom Layer, 127 vias
v2: diameter 32, hole 16, Top Layer to Bottom Layer, 19 vias
v3: diameter 19.68, hole 7.87, Top Layer to Bottom Layer, 17 vias

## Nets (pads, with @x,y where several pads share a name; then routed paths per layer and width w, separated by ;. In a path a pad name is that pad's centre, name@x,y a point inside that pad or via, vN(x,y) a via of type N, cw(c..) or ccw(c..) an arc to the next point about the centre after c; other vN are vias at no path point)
DEMAG: C1.2 R1.2 R2.1 S1.2 U1.18 U2.18 U3.18 | length 5118.1
  Top Layer w10: v1(1706.4,4561.11) 1724.4,4543.11 U1.18@1753.55,4543.11 ; v1(1709,1295) 1727,1277 U3.18@1756.15,1277 ; v1(1709,2930) 1727,2912 U2.18@1756.15,2912 ; v1(1710,430) 1715,425 S1.2@1767.07,425 ; R1.2@1797.5,335 1797.5,376.5 1767.07,406.93 S1.2@1767.07,425 ; R2.1@1803.5,580 C1.2@1803.5,515 1803.5,478.5 1767.07,442.07 S1.2@1767.07,425
  Bottom Layer w10: v1(1706.4,4561.11) 1706.4,4383.6 1945,4145 1945,3391.83 1833.17,3280 1754,3280 1709,3235 v1(1709,2930) 1709,2771 1945,2535 1945,1753.21 1836.79,1645 1749,1645 1709,1605 v1(1709,1295) 1711.3,1292.7 1710,1291.4 v1(1710,430)
ER-U: D12.1 J13.9 U3.19 | length 4408
  Top Layer w10: U3.19@1756.15,1257.32 1716.32,1257.32 1702,1243 1702,822.46 1833,691.46 D12.1@2125.02,691.46 2162.02,654.46 2738.46,654.46 2971,887 2971,2149 3193,2371 3193,2945 3272,3024 3449,3024 J13.9@3487,3062
ER-V: D4.1 J13.5 U2.19 | length 3050.7
  Top Layer w10: U2.19@1756.15,2892.32 1716.32,2892.32 1702,2878 1702,2457 1834,2325 1988.96,2325 D4.1@2017.5,2353.54 2052.5,2318.54 2864.54,2318.54 3130,2584 3130,3118 3236,3224 3449,3224 J13.5@3487,3262
ER-W: D6.1 J13.1 U1.19 | length 2558.6
  Top Layer w10: U1.19@1753.55,4523.43 1713.72,4523.43 1699.4,4509.11 1699.4,4089.6 1821.27,3967.73 D6.1@2027.48,3967.73 2062.48,3932.73 2727.27,3932.73 3236,3424 3449,3424 J13.1@3487,3462
GND: C2.2 C3.2 C4.2 C5.2 C6.2 C7.2 C8.2 C9.2 C10.2 C11.2 C12.2 C13.2 C14.2 C15.2 C16.2 C17.2 C18.2 C19.2 C20.2 C21.2 C22.2 C23.1 C24.1 C25.2 C26.2 C27.2 C28.1 C29.2 C30.2 C31.1 C32.1 D1.1 D2.1 D3.1 D8.1 D9.1 D10.1 D16.1 J4.2 J4.3 J4.4 J4.5 J5.2 J5.3 J5.4 J5.5 J6.2 J6.3 J6.4 J6.5 J7.2 J8.2 J9.2 J10.3 J11.2 J11.3 J13.4 J13.8 J13.12 J13.15 J13.16 J13.17 J13.20 J14.1 J15.1 R1.1 R9.2 R10.2 R11.2 R31.2 R32.2 R33.2 R48.2 R49.2 R50.2 R60.2 R61.2 R62.2 R69.1 R70.1 R71.1 R74.2 R85.2 U1.7 U1.10 U1.16 U1.17 U1.21 U2.7 U2.10 U2.16 U2.17 U2.21 U3.7 U3.10 U3.16 U3.17 U3.21 U4.4 U5.4 U6.4 U7.4 U8.1 | length 4261.3
  Top Layer w10: U1.17@1753.55,4562.8 1798.09,4562.8 1801.9,4566.61 1786.03,4582.48 U1.16@1753.55,4582.48 ; U3.17@1756.15,1296.69 1800.69,1296.69 1804.5,1300.5 1788.63,1316.37 U3.16@1756.15,1316.37 ; U2.17@1756.15,2931.69 1800.69,2931.69 1804.5,2935.5 1788.63,2951.37 U2.16@1756.15,2951.37 ; U1.7@1897.25,4523.43 1845.09,4523.43 U1.21@1825.4,4543.11 1864.77,4582.48 U1.10@1897.25,4582.48 1937.77,4582.48 1952.35,4597.06 C2.2@2006.4,4597.06 ; U3.7@1899.85,1257.32 1847.68,1257.32 U3.21@1828,1277 1867.37,1316.37 U3.10@1899.85,1316.37 1940.37,1316.37 1954.95,1330.95 ; U2.7@1899.85,2892.32 1847.68,2892.32 U2.21@1828,2912 1867.37,2951.37 U2.10@1899.85,2951.37 1940.37,2951.37 1954.95,2965.95 ; C29.2@3259.71,1512.56 3277.46,1530.31 U8.1@3277.46,1602.76
  Top Layer w15: C23.1@3053.47,4322.48 R74.2@3053.47,4382.48
  Top Layer w20: R1.1@1860.5,335 v1(1909,335) ; 1954.95,1330.95 C4.2@2009,1330.95 C7.2@2064,1330.95 v1(2103.06,1330.95) ; 1954.95,2965.95 C3.2@2009,2965.95 C6.2@2064,2965.95 v1(2103.06,2965.95) ; v1(1989,1950) 2046.4,1892.6 D3.1@2046.4,1852.24 ; v1(1989,3585) 2046.4,3527.6 D2.1@2046.4,3487.24 ; C2.2@2006.4,4597.06 C5.2@2061.4,4597.06 v1(2100.46,4597.06) ; D1.1@2043.8,5118.35 v1(2043.8,5163.51) ; R9.2@2076.73,4137.5 2076.73,4082.27 v1(2109,4050) ; v1(2079,830) R11.2@2079,873.5 ; R10.2@2079,2508.5 2079,2466 v1(2080,2465) ; D8.1@2173.8,5118.35 v1(2173.8,5163.51) ; D10.1@2176.4,1852.24 v1(2176.4,1897.4) ; D9.1@2176.4,3487.24 v1(2176.4,3532.4) ; v1(2206.73,4094) R31.2@2206.73,4137.5 ; v1(2209,830) R33.2@2209,873.5 ; v1(2209,2465) R32.2@2209,2508.5 ; v1(2247.4,4736.11) C8.2@2290.91,4736.11 ; v1(2250,1470) C10.2@2293.5,1470 ; v1(2250,3105) C9.2@2293.5,3105 ; v1(2261.48,5182.48) 2262.98,5183.98 C11.2@2306.48,5183.98 ; v1(2264,1915) 2265.5,1916.5 C14.2@2309,1916.5 ; v1(2264,3550) 2265.5,3551.5 C13.2@2309,3551.5 ; v1@2277.48,2700 C15.2@2312.48,2735 ; v1(2309.91,4317.61) C12.2@2309.91,4366.11 ; v1(2312.5,1051.5) C16.2@2312.5,1100 ; v1(2330,4100) 2336.73,4106.73 R48.2@2336.73,4137.5 ; v1(2339,830) R50.2@2339,873.5 ; R49.2@2339,2508.5 2339,2461 v1(2340,2460) ; C17.2@2356.4,4562.61 v1(2447.39,4562.61) ; C19.2@2359,1301.5 v1(2401.5,1301.5) ; C18.2@2359.5,2936 v1(2401.99,2936) ; R60.2@2466.73,4137.5 2469.24,4135 v1(2539,4135) ; v1(2469,830) R62.2@2469,873.5 ; R61.2@2469,2508.5 2518.5,2508.5 v1(2520,2510) ; U4.4@2469,4813.39 2469,4752.17 C20.2@2484,4737.17 2484.8,4736.37 v1(2554.08,4736.37) ; U6.4@2471.52,1545.91 2471.52,1484.69 C22.2@2486.52,1469.69 2486.83,1470 v1(2540,1470) ; U5.4@2471.52,3180.91 2471.52,3119.69 C21.2@2486.52,3104.69 v1(2530.69,3104.69) ; v1(2591.48,4832.48) R69.1@2591.48,4880.99 ; v1(2594,1565) R71.1@2594,1613.5 ; v1(2594,3200) R70.1@2594,3248.5 ; v1(3004.18,4322.48) C23.1@3053.47,4322.48 ; v2(3153.18,4272.48) U7.4@3207.68,4272.48 ; v2(3373,4554) 3372,4555 3419.84,4555 C24.1@3425,4560.16 ; C30.2@3399,2782.5 3419.82,2761.68 3420.14,2762 J13.15@3487,2762 ; v1(3425.18,4076.52) C31.1@3425.18,4125.81 ; R85.2@3581.46,4332.48 3581.46,4260.2 3581.66,4260 v1(3581.66,4225)
  other v1: 2277.48,2697.5
  other v2: 3119,1440 3189,1440 3119,1510 3189,1510 3044,1680 3044,1770 3044,1860
  other v3: 1828,1242.55 1793.55,1277 1862.45,1277 1828,1311.45 1828,2877.55 1793.55,2912 1862.45,2912 1828,2946.45 1825.4,4508.66 1790.95,4543.11 1859.85,4543.11 1825.4,4577.56
GND_FAULT: D17.1 J10.2 R78.2 R80.2 | length 794
  Top Layer w20: J10.2@3049,5180 3049,4976 3319.43,4705.57 R80.2@3319.43,4562.98 R78.2@3254.43,4562.98
GSEL0: R18.1 R20.1 R31.1 R33.1 R90.1 U1.1 U3.1 | length 4675.3
  Top Layer w10: U1.1@1786.03,4471.26 1786.03,4336.48 1876.4,4246.11 v1(2141.4,4246.11) R18.1@2141.4,4202.61 ; U3.1@1788.63,1205.15 1788.63,1070.37 1879,980 v1(2144,980) R20.1@2144,936.5 ; R18.1@2140.24,4200.5 R18.1@2141.73,4200.5 R31.1@2206.73,4200.5 ; R20.1@2142.5,936.5 R20.1@2144,936.5 ; R33.1@2209,936.5 R20.1@2144,936.5
  Bottom Layer w10: v1(2144,980) 2033,1091 2033,2649.5 R90.1@2080,2696.5 2078.5,2696.5 2035,2740 2035,4141 v1@2144,4250
GSEL1: R6.1 R8.1 R9.1 R11.1 R91.1 U1.20 U3.20 | length 4480.5
  Top Layer w10: U1.20@1753.55,4503.74 1753.55,4288.96 1839.51,4203 v1@1964,4203 ; U3.20@1756.15,1237.63 1756.15,1022.85 1842.11,936.89 v1@1966.6,936.89 ; v1(1964.33,4200.89) 2011.34,4200.89 R6.1@2011.73,4200.5 R9.1@2076.73,4200.5 ; v1(1966.99,936.5) R8.1@2014,936.5 R11.1@2079,936.5
  Bottom Layer w10: v1(1964.33,4200.89) 2015,4150.22 2015,2731.5 R91.1@1980,2696.5 2015,2661.5 2015,984.5 v1(1966.99,936.5)
NetC8_1: C8.1 R39.2 U4.2 U4.5 | length 403.1
  Top Layer w15: R39.2@2353.9,4671.11 C8.1@2353.9,4736.11 2353.9,4760.81 2368.92,4775.83 2368.92,4867.63 v1(2422.4,4921.11) ; v1(2468.92,4972.63) U4.5@2468.92,5026.58
  Bottom Layer w15: v1(2422.4,4921.11) 2468.92,4967.63 v1(2468.92,4972.63)
NetC9_1: C9.1 R41.2 U5.2 U5.5 | length 403.1
  Top Layer w15: R41.2@2356.5,3040 C9.1@2356.5,3105 2356.5,3129.7 2371.52,3144.72 U5.2@2371.52,3180.91 2371.52,3236.52 v1(2425,3290) ; v1(2471.52,3341.52) U5.5@2471.52,3395.47
  Bottom Layer w15: v1(2425,3290) 2471.52,3336.52 v1(2471.52,3341.52)
NetC10_1: C10.1 R42.2 U6.2 U6.5 | length 403.1
  Top Layer w15: R42.2@2356.5,1405 C10.1@2356.5,1470 2356.5,1494.7 2371.52,1509.72 U6.2@2371.52,1545.91 2371.52,1601.52 v1(2425,1655) ; v1(2471.52,1706.52) U6.5@2471.52,1760.47
  Bottom Layer w15: v1(2425,1655) 2471.52,1701.52 v1(2471.52,1706.52)
NetC23_2: C23.2 R73.2 R74.1 R75.1 U7.3 | length 277.8
  Top Layer w15: R75.1@3126.16,4505 3116.46,4495.3 R73.2@3116.46,4442.48 R74.1@3116.46,4382.48 C23.2@3116.46,4322.48 U7.3@3207.68,4322.48
NetC29_1: C29.1 D18.1 J12.1 U8.2 U8.3 U8.4
NetC31_2: C31.2 R77.2 R79.2 R81.2 U7.2 U7.5 | length 535.9
  Top Layer w15: U7.2@3207.68,4372.48 3255.18,4372.48 3355.18,4272.48 U7.5@3422.25,4272.48 3422.25,4191.73 C31.2@3425.01,4188.98 ; R77.2@3229.97,4188.98 R79.2@3294.97,4188.98 R81.2@3359.97,4188.98 C31.2@3425.01,4188.98 ; C31.2@3425.18,4188.8 C31.2@3425.01,4188.98
NetC32_2: C32.2 R84.2 R85.1 U7.6 | length 220.4
  Top Layer w15: U7.6@3422.25,4322.48 3465.14,4322.48 3475.14,4332.48 R85.1@3518.47,4332.48 ; C32.2@3518.47,4272.48 R85.1@3518.47,4332.48 ; R84.2@3518.47,4392.48 R85.1@3518.47,4332.48
NetD1_3: D1.3 T1.10 U1.12 | length 1512.8
  Top Layer w10: T1.10@929.35,5047.05 990.46,5047.05 1031.4,5006.11 1647.4,5006.11 v1(1772.4,4881.11) ; U1.12@1845.09,4614.96 1845.09,4659.79 v1(1851.4,4666.11) ; v1@1962.4,5023.87 D1.3@2006.4,5023.87
  Bottom Layer w10: v1(1851.4,4666.11) 1851.4,4802.11 v1(1772.4,4881.11) 1826.02,4881.11 v1@1968.78,5023.87
  other v1: 1962.4,5021.11
NetD2_3: D2.3 T2.10 U2.12 | length 1512.8
  Top Layer w10: T2.10@931.95,3415.94 993.06,3415.94 1034,3375 1650,3375 v1(1775,3250) ; U2.12@1847.68,2983.85 1847.68,3028.68 v1(1854,3035) ; v1@1965,3392.76 D2.3@2009,3392.76
  Bottom Layer w10: v1(1854,3035) 1854,3171 v1(1775,3250) 1828.62,3250 v1(1971.38,3392.76)
NetD3_3: D3.3 T3.10 U3.12 | length 1506.4
  Top Layer w10: T3.10@931.95,1780.94 993.06,1780.94 1034,1740 1650,1740 v1(1775,1615) ; U3.12@1847.68,1348.85 1847.68,1393.68 v1(1854,1400) ; v1(1975,1757.76) D3.3@2009,1757.76
  Bottom Layer w10: v1(1854,1400) 1854,1536 v1(1775,1615) 1832.24,1615 v1(1975,1757.76)
NetD4_2: D4.2 R21.1 | length 67
  Top Layer w10: D4.2@2080.5,2353.54 R21.1@2147.5,2353.54
NetD5_2: D5.2 R22.1 | length 67
  Top Layer w10: D5.2@2080.5,2258.54 R22.1@2147.5,2258.54
NetD6_2: D6.2 R23.1 | length 67
  Top Layer w10: D6.2@2090.47,3967.73 R23.1@2157.48,3967.73
NetD7_2: D7.2 R24.1 | length 67
  Top Layer w10: D7.2@2090.47,3872.73 R24.1@2157.48,3872.73
NetD8_3: D8.3 R3.1 R12.1 T1.9 U1.14 | length 1654.1
  Top Layer w10: T1.9@929.35,4948.62 988.91,4948.62 1026.4,4986.11 1629.32,4986.11 1805.72,4809.72 ; U1.14@1805.72,4614.96 1805.72,4809.72 ; D8.3@2136.4,5023.87 2105.16,5023.87 2090.31,5009.02 R12.1@2090.31,4931.11 2078.23,4943.2 R3.1@1996.4,4943.2 1996.4,4910.11 1984.4,4898.11 1894.11,4898.11 1805.72,4809.72
NetD9_3: D9.3 R4.1 R14.1 T2.9 U2.14 | length 1654.1
  Top Layer w10: T2.9@931.95,3317.51 991.51,3317.51 1029,3355 1631.92,3355 1808.31,3178.61 ; U2.14@1808.31,2983.85 1808.31,3178.61 ; D9.3@2139,3392.76 2107.76,3392.76 2092.91,3377.91 R14.1@2092.91,3300 2080.83,3312.09 R4.1@1999,3312.09 1999,3279 1987,3267 1896.71,3267 1808.31,3178.61
NetD10_3: D10.3 R5.1 R16.1 T3.9 U3.14 | length 1654.1
  Top Layer w10: T3.9@931.95,1682.51 991.51,1682.51 1029,1720 1631.92,1720 1808.31,1543.61 ; U3.14@1808.31,1348.85 1808.31,1543.61 ; D10.3@2139,1757.76 2107.76,1757.76 2092.91,1742.91 R16.1@2092.91,1665 2080.83,1677.09 R5.1@1999,1677.09 1999,1644 1987,1632 1896.71,1632 1808.31,1543.61
NetD11_2: D11.2 R34.1 | length 67
  Top Layer w10: D11.2@2186.52,596.46 R34.1@2253.53,596.46
NetD12_2: D12.2 R35.1 | length 67
  Top Layer w10: D12.2@2188.02,691.46 R35.1@2255.02,691.46
NetD13_2: D13.2 R63.1 | length 66.4
  Top Layer w15: D13.2@2438.92,5110.99 2504.08,5110.99 R63.1@2504.99,5110.08
NetD14_2: D14.2 R64.1 | length 69.1
  Top Layer w15: D14.2@2441.44,3478.5 2496.44,3478.5 R64.1@2506.44,3488.5
NetD15_2: D15.2 R65.1 | length 69.1
  Top Layer w15: D15.2@2441.44,1843.5 2496.44,1843.5 R65.1@2506.44,1853.5
NetD16_2: D16.2 R76.1 | length 85
  Top Layer w20: D16.2@3175.5,1940 3255.5,1940 R76.1@3259,1936.5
